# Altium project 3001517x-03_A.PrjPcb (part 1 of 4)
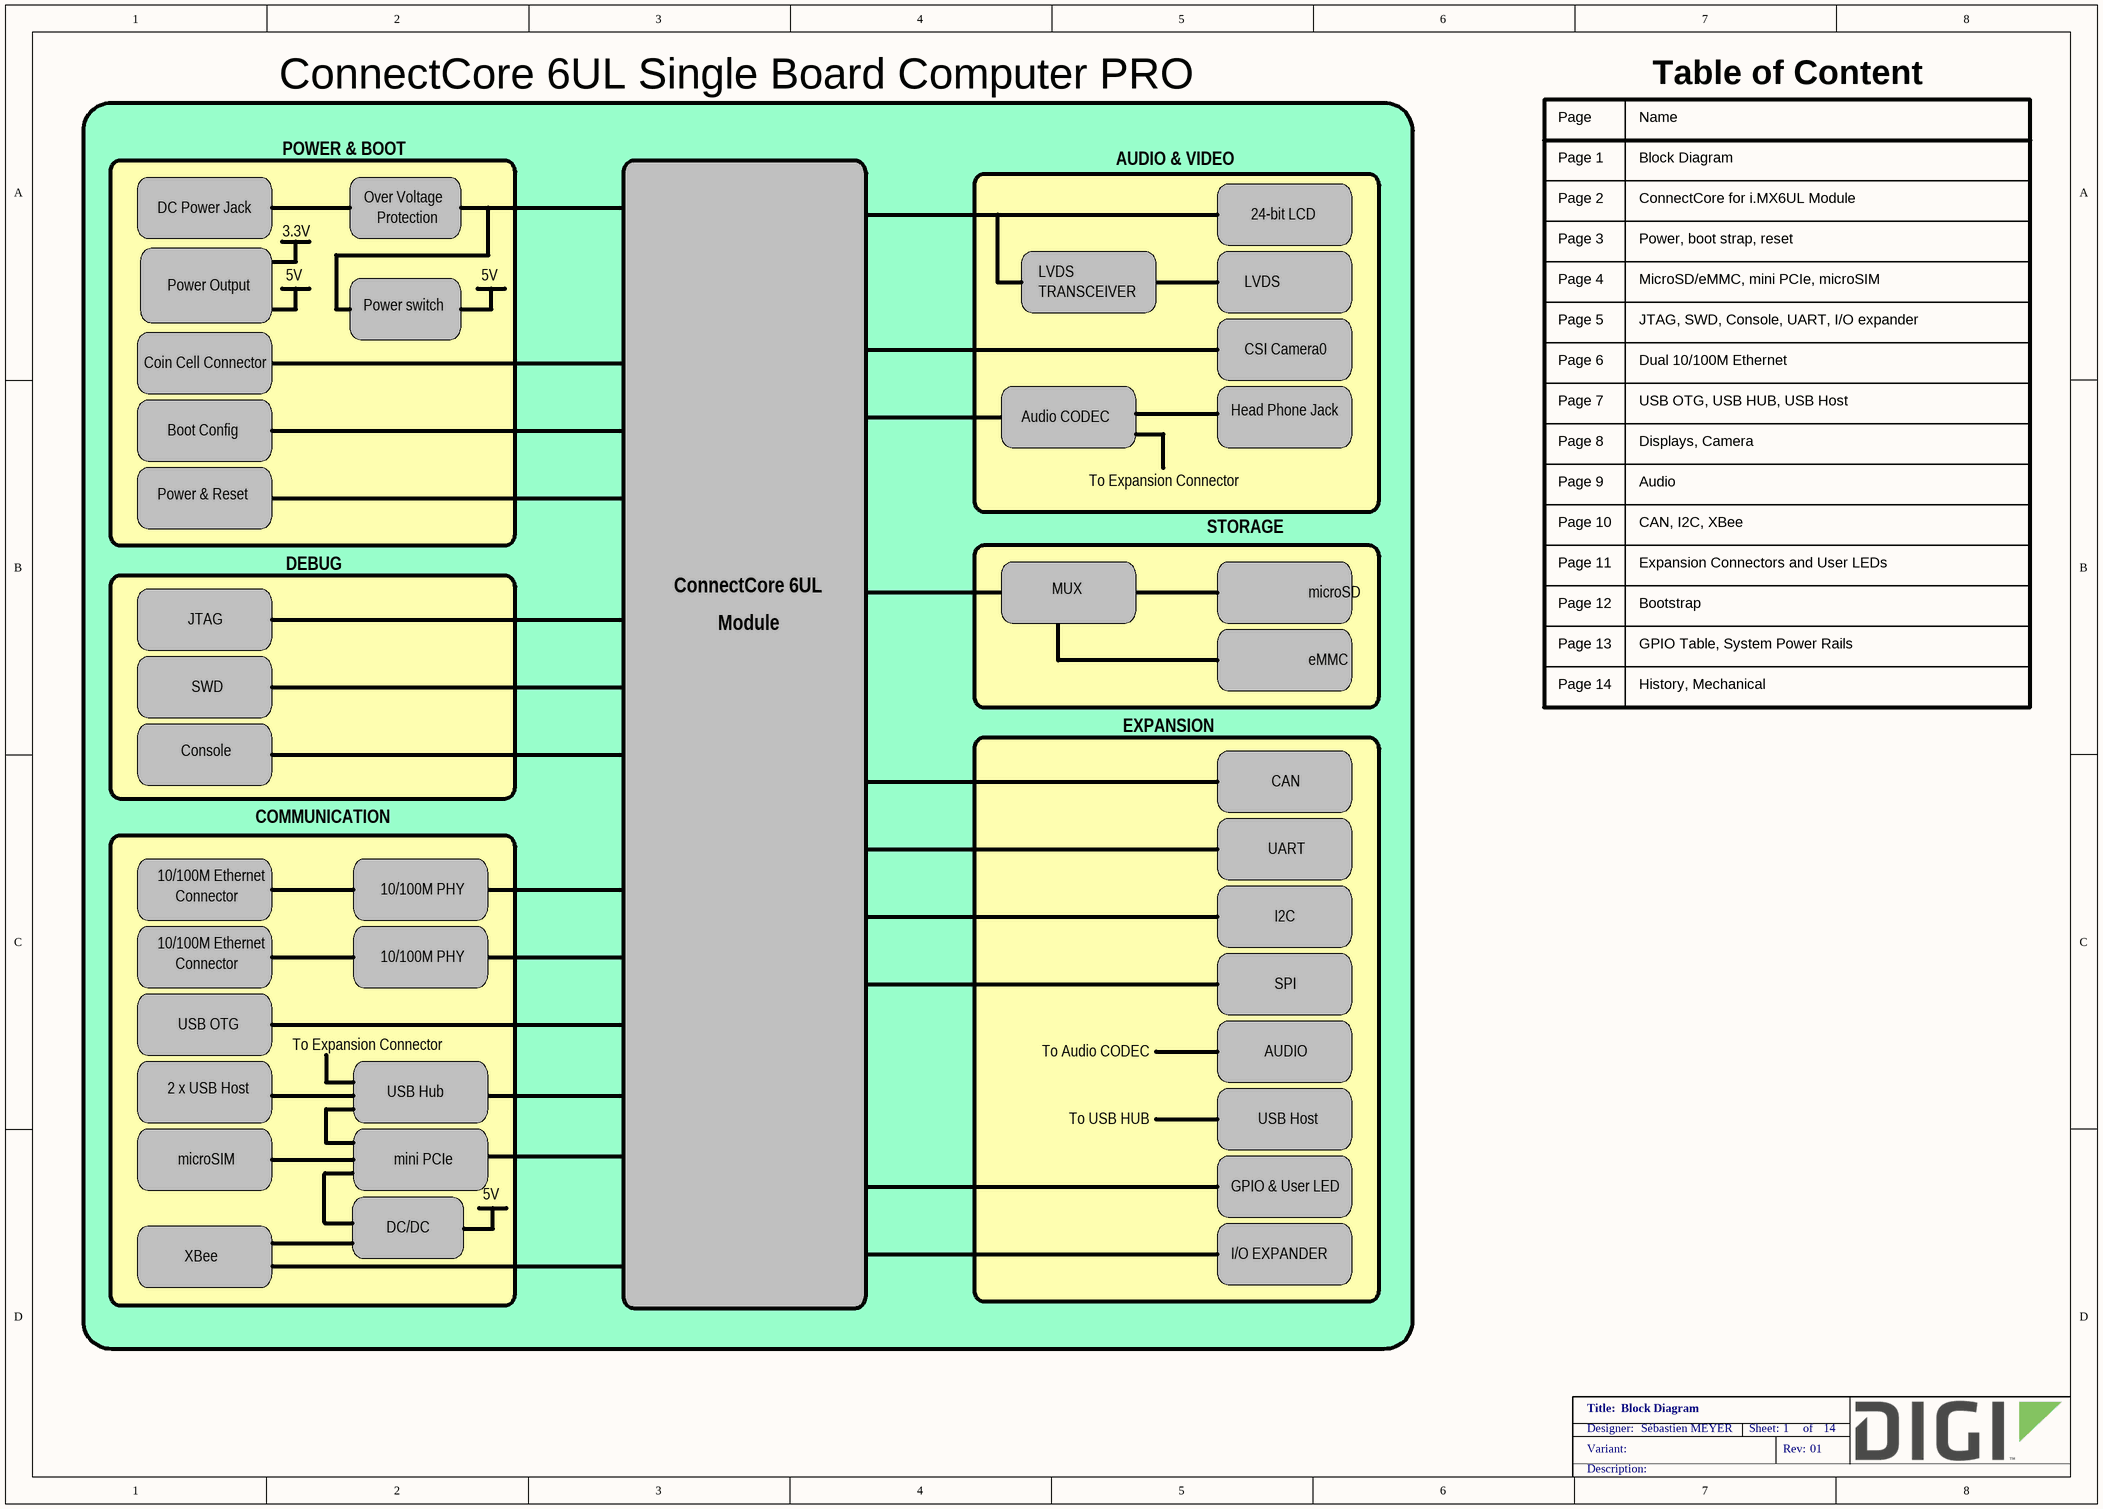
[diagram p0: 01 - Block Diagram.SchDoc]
VariantRevision: 01
14 sheets, 603 parts. Net scope: flat (ports and power ports of the same name join across sheets).
Board file: 3001517x-03_A.PcbDoc
Sheets:
  01 - Block Diagram.SchDoc
  02 - CCIMX6UL Module.SchDoc
  03 - Power, boot strap, reset.SchDoc
  04 - MicroSD, eMMC, Mini PCIe, microSIM.SchDoc
  05 - JTAG, SWD, Console, UART, IO expander.SchDoc
  06 - Ethernet.SchDoc
  07 - USB OTG, USB HUB, USB Host.SchDoc
  08 - Displays and camera.SchDoc
  09 - Audio.SchDoc
  10 - CAN, I2C, XBee.SchDoc
  11 - Expansion Connectors, User LEDs, NTAG.SchDoc
  12 - Bootstrap.SchDoc
  13 - GPIO Table, System Power rails.SchDoc
  14 - History, Mechanicals.SchDoc

## Sheet 01 - Block Diagram.SchDoc: Block Diagram
size A3; PageSetup: Record=PageOptions¦CenterHorizontal=True¦CenterVertical=True¦PrintScale=0.70¦XCorrection=1.00¦YCorrection=1.00¦PrintKind=0¦BorderSize=5000000¦LeftOffset=0¦BottomOffset=0¦Orientation=2¦PaperLength=4200¦PaperWidth=2970¦Scale=100¦PaperSource=7¦PrintQuality=600¦MediaType=1¦DitherType=10¦PaperKind=A4¦PrintScaleMode=1; Author: Sébastien MEYER; SheetNumber: 1; SheetTotal: 14

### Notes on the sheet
- ConnectCore 6UL Single Board Computer PRO
- Table of Content
- POWER & BOOT
- AUDIO & VIDEO
- Page 1
- Page
- Block Diagram
- Name
- DC Power Jack
- 3.3V
- Protection
- Over Voltage
- 24-bit LCD
- Page 2
- Page 3
- ConnectCore for i.MX6UL Module
- Power, boot strap, reset
- Power Output
- 5V
- Power switch
- LVDS
- TRANSCEIVER
- Page 4
- MicroSD/eMMC, mini PCIe, microSIM
- Coin Cell Connector
- CSI Camera0
- Page 5
- Page 6
- Dual 10/100M Ethernet
- JTAG, SWD, Console, UART, I/O expander
- Boot Config
- Audio CODEC
- Head Phone Jack
- Page 7
- Page 8
- Displays, Camera
- USB OTG, USB HUB, USB Host
- Power & Reset
- To Expansion Connector
- Page 9
- Audio
- DEBUG
- STORAGE
- Page 10
- Page 11
- CAN, I2C, XBee
- Expansion Connectors and User LEDs
- JTAG
- ConnectCore 6UL
- Module
- MUX
- microSD
- Page 12
- Page 13
- GPIO Table, System Power Rails
- Bootstrap
- SWD
- eMMC
- Page 14
- History, Mechanical
- Console
- EXPANSION
- CAN
- COMMUNICATION
- UART
- 10/100M Ethernet
- Connector
- 10/100M PHY
- I2C
- SPI
- USB OTG
- To Audio CODEC
- AUDIO
- 2 x USB Host
- USB Hub
- To USB HUB
- USB Host
- microSIM
- mini PCIe
- GPIO & User LED
- XBee
- DC/DC
- I/O EXPANDER

## Sheet 02 - CCIMX6UL Module.SchDoc: ConnectCore for i.MX6UL module
size A2; PageSetup: Record=PageOptions¦CenterHorizontal=True¦CenterVertical=True¦PrintScale=0.71¦XCorrection=1.00¦YCorrection=1.00¦PrintKind=0¦BorderSize=5000000¦LeftOffset=0¦BottomOffset=0¦Orientation=2¦PaperLength=4200¦PaperWidth=2970¦Scale=100¦PaperSource=257¦PrintQuality=600¦MediaType=1¦DitherType=10¦PrintScaleMode=1¦PaperKind=A3¦PaperIndex=8; Author: Sébastien MEYER; SheetNumber: 2; SheetTotal: 14
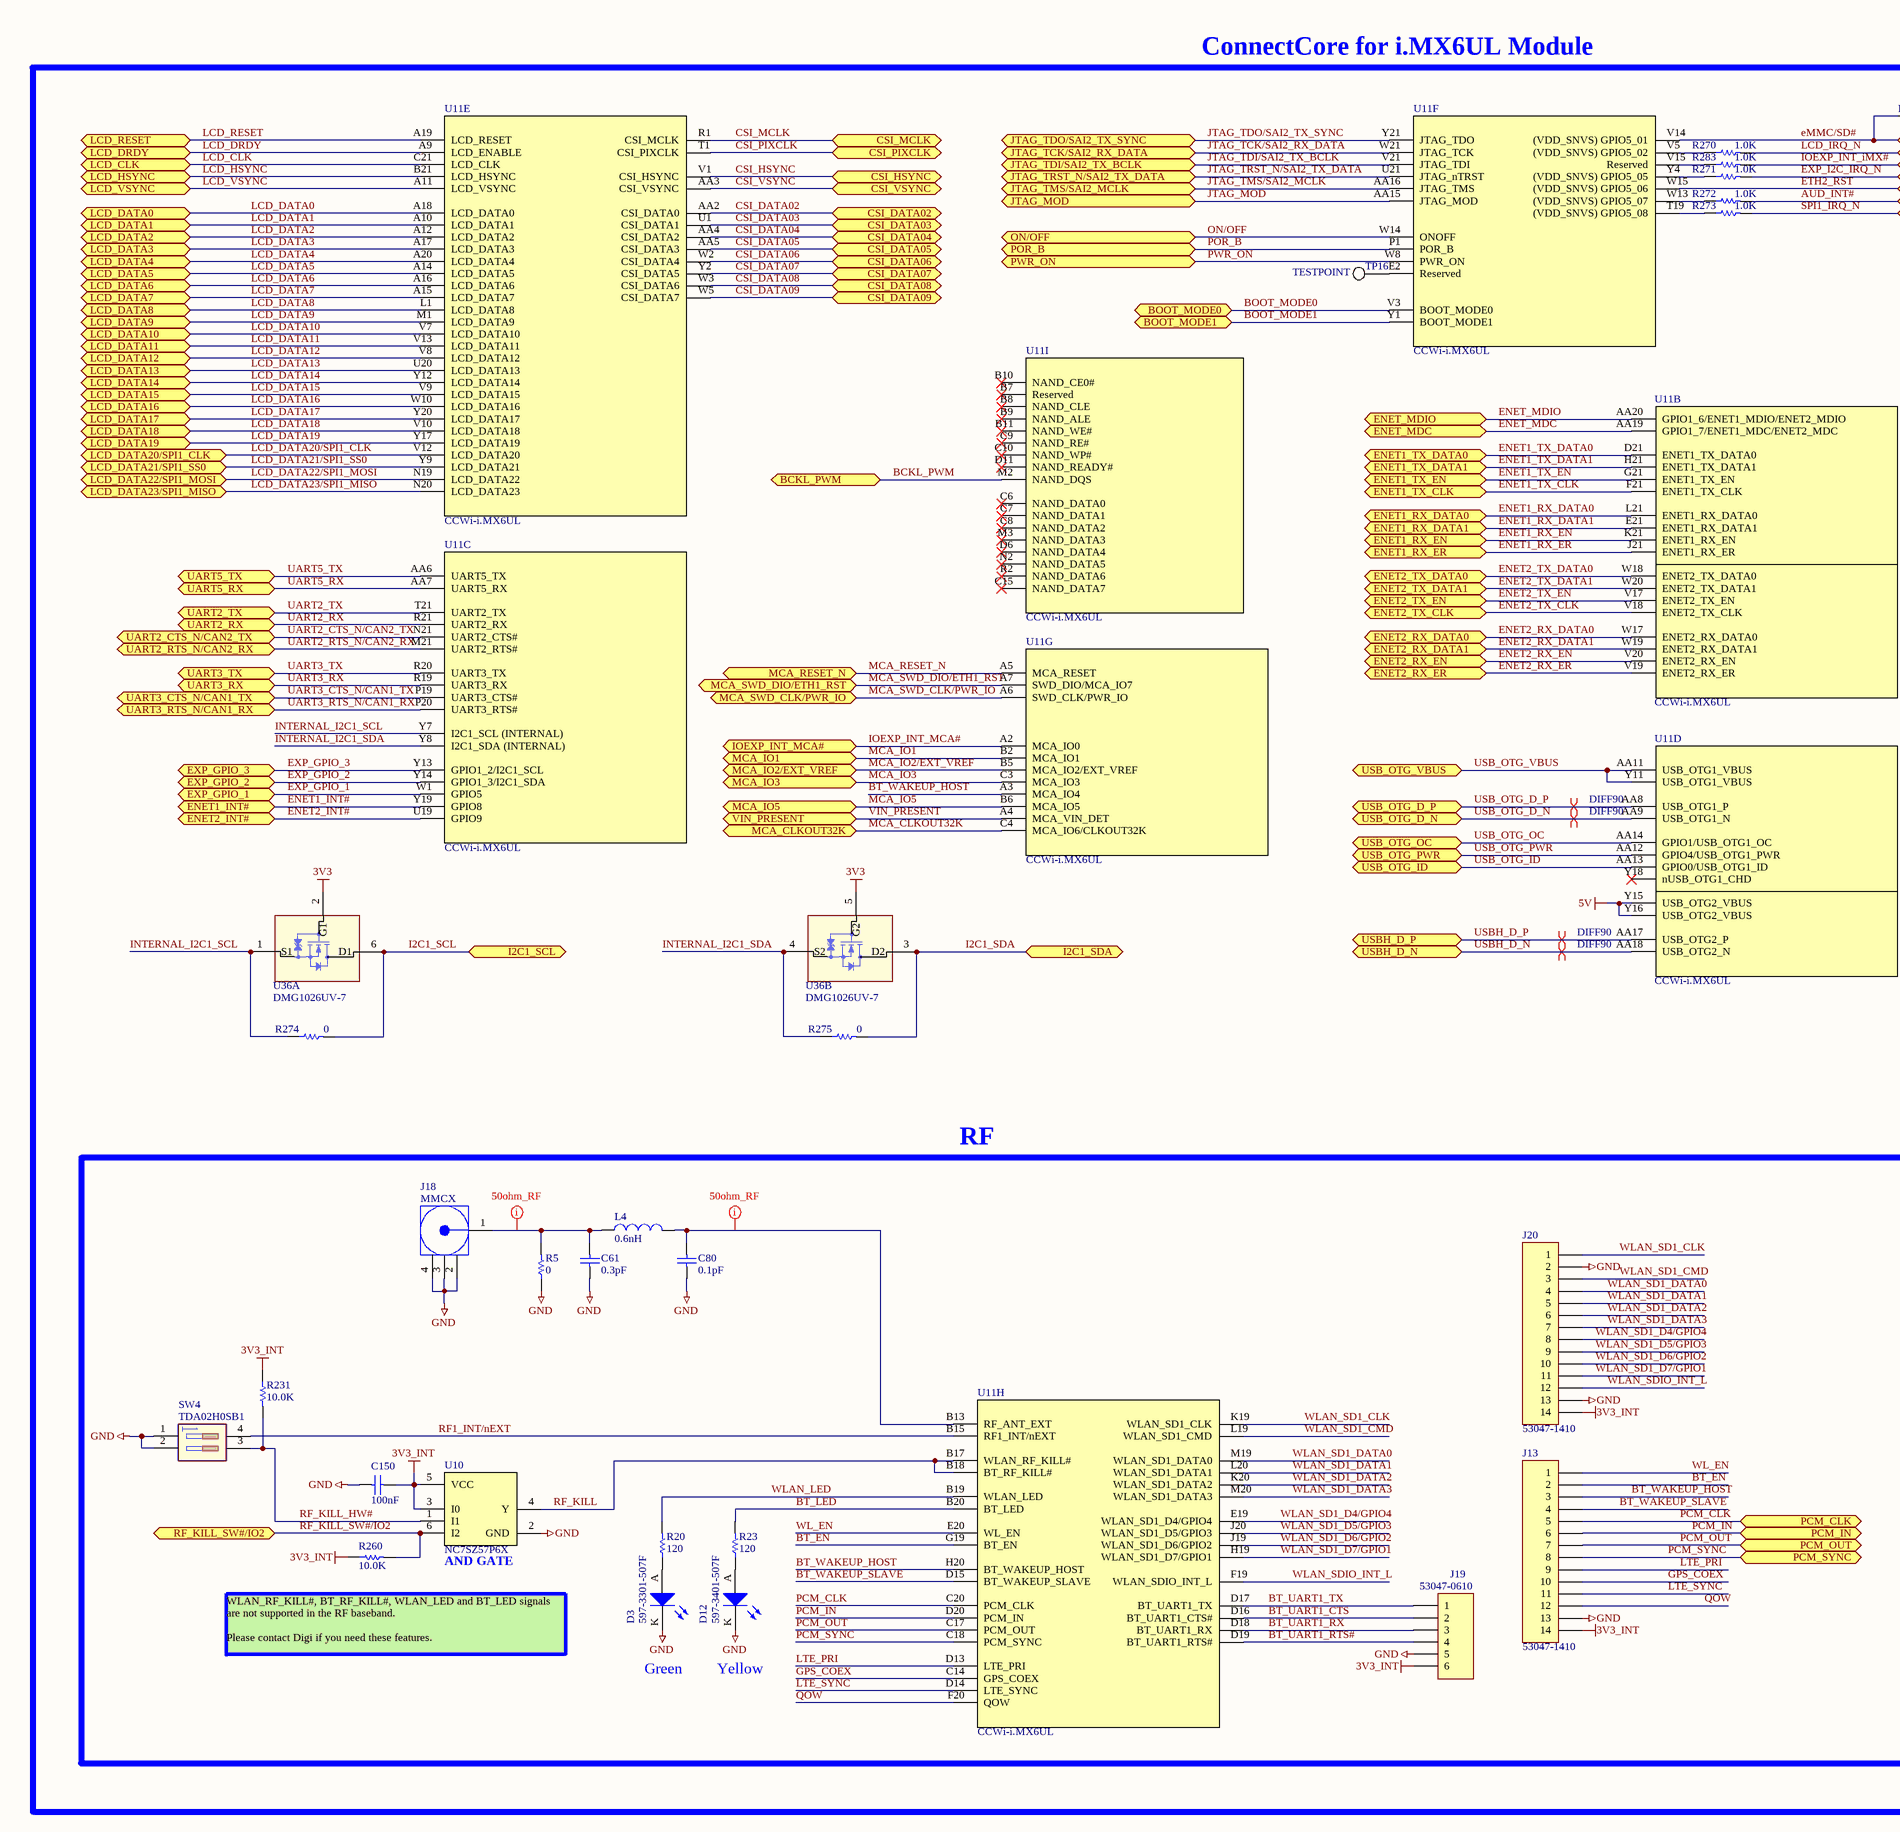
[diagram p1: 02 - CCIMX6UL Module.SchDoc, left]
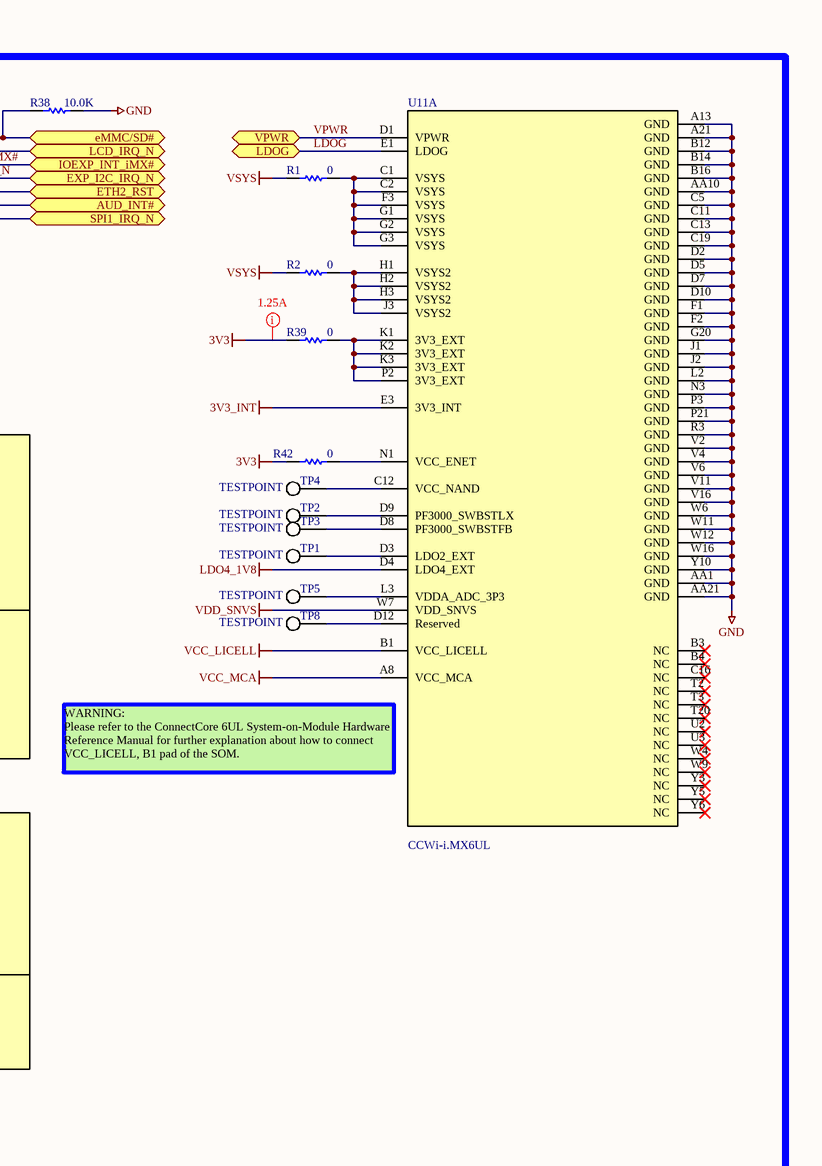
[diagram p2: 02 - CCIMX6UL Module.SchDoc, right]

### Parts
C61  0.3pF  [CAPC0603X33AL]
C80  0.1pF  [CAPC0603X33AL]
C150  100nF  [CAPC1005X55N]
D3  597-3301-507F  [LEDM3020X130N]
D12  597-3401-507F  [LEDM3020X130N]
J13  Manufacturer_Part_Number: 53047-1410  [MOLEX_53047-1410]  (hidden comment: 1x14P)
J18  MMCX  [AMPHENOL_908-22101]
J19  Manufacturer_Part_Number: 53047-0610  [MOLEX_53047-0610]  (hidden comment: 1x6P)
J20  Manufacturer_Part_Number: 53047-1410  [MOLEX_53047-1410]  (hidden comment: 1x14P)
L4  0.6nH  [INDC0603X33N]
R1  0  [RESC1609X55N]
R2  0  [RESC1609X55N]
R5  0  [RESC0603X33AL]
R20  120  [RESC1005X40N]
R23  120  [RESC1005X40N]
R38  10.0K  [RESC1005X40N]
R39  0  [RESC1609X55N]
R42  0  [RESC1005X40N]
R231  10.0K  [RESC1005X40N]
R260  10.0K  [RESC1005X40N]
R270  1.0K  [RESC1005X40N]
R271  1.0K  [RESC1005X40N]
R272  1.0K  [RESC1005X40N]
R273  1.0K  [RESC1005X40N]
R274  0  [RESC1005X40N]
R275  0  [RESC1005X40N]
R283  1.0K  [RESC1005X40N]
SW4  TDA02H0SB1  [SW_TDA02]
TP1  TESTPOINT  [TP0762]  (no BOM)
TP2  TESTPOINT  [TP0762]  (no BOM)
TP3  TESTPOINT  [TP0762]  (no BOM)
TP4  TESTPOINT  [TP0762]  (no BOM)
TP5  TESTPOINT  [TP0762]  (no BOM)
TP8  TESTPOINT  [TP0762]  (no BOM)
TP16  TESTPOINT  [TP0762]  (no BOM)
U10  NC7SZ57P6X  [SOT65P210X110-6N]
U11  CCWi-i.MX6UL  [CC6UL_LGA]  (parts A,B,C,D,E,F,G,H,I of 9)
U36  DMG1026UV-7  [SOTFL50P160X60-6N]  (parts A,B of 2)

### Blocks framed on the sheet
RF: C61 C80 C150 D3 D12 J13 J18-J20 L4 R5 R20 R23 R231 R260 SW4 U10 U11

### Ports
AUD_INT# (bidir), BCKL_PWM (bidir), BOOT_MODE0 (bidir), BOOT_MODE1 (bidir), CSI_DATA02 (bidir), CSI_DATA03 (bidir), CSI_DATA04 (bidir), CSI_DATA05 (bidir), CSI_DATA06 (bidir), CSI_DATA07 (bidir), CSI_DATA08 (bidir), CSI_DATA09 (bidir), CSI_HSYNC (bidir), CSI_MCLK (bidir), CSI_PIXCLK (bidir), CSI_VSYNC (bidir), eMMC/SD# (bidir), ENET1_INT# (bidir), ENET1_RX_DATA0 (bidir), ENET1_RX_DATA1 (bidir), ENET1_RX_EN (bidir), ENET1_RX_ER (bidir), ENET1_TX_CLK (bidir), ENET1_TX_DATA0 (bidir), ENET1_TX_DATA1 (bidir), ENET1_TX_EN (bidir), ENET2_INT# (bidir), ENET2_RX_DATA0 (bidir), ENET2_RX_DATA1 (bidir), ENET2_RX_EN (bidir), ENET2_RX_ER (bidir), ENET2_TX_CLK (bidir), ENET2_TX_DATA0 (bidir), ENET2_TX_DATA1 (bidir), ENET2_TX_EN (bidir), ENET_MDC (bidir), ENET_MDIO (bidir), ETH2_RST (bidir), EXP_GPIO_1 (bidir), EXP_GPIO_2 (bidir), EXP_GPIO_3 (bidir), EXP_I2C_IRQ_N (bidir), I2C1_SCL (bidir), I2C1_SDA (bidir), IOEXP_INT_iMX# (bidir), IOEXP_INT_MCA# (bidir), JTAG_MOD (bidir), JTAG_TCK/SAI2_RX_DATA (bidir), JTAG_TDI/SAI2_TX_BCLK (bidir), JTAG_TDO/SAI2_TX_SYNC (bidir), JTAG_TMS/SAI2_MCLK (bidir), JTAG_TRST_N/SAI2_TX_DATA (bidir), LCD_CLK (bidir), LCD_DATA0 (bidir), LCD_DATA1 (bidir), LCD_DATA2 (bidir), LCD_DATA3 (bidir), LCD_DATA4 (bidir), LCD_DATA5 (bidir), LCD_DATA6 (bidir), LCD_DATA7 (bidir), LCD_DATA8 (bidir), LCD_DATA9 (bidir), LCD_DATA10 (bidir), LCD_DATA11 (bidir), LCD_DATA12 (bidir), LCD_DATA13 (bidir), LCD_DATA14 (bidir), LCD_DATA15 (bidir), LCD_DATA16 (bidir), LCD_DATA17 (bidir), LCD_DATA18 (bidir), LCD_DATA19 (bidir), LCD_DATA20/SPI1_CLK (bidir), LCD_DATA21/SPI1_SS0 (bidir), LCD_DATA22/SPI1_MOSI (bidir), LCD_DATA23/SPI1_MISO (bidir), LCD_DRDY (bidir), LCD_HSYNC (bidir), LCD_IRQ_N (bidir), LCD_RESET (bidir), LCD_VSYNC (bidir), LDOG (bidir), MCA_CLKOUT32K (bidir), MCA_IO1 (bidir), MCA_IO2/EXT_VREF (bidir), MCA_IO3 (bidir), MCA_IO5 (bidir), MCA_RESET_N (bidir), MCA_SWD_CLK/PWR_IO (bidir), MCA_SWD_DIO/ETH1_RST (bidir), ON/OFF (bidir), PCM_CLK (bidir), PCM_IN (bidir), PCM_OUT (bidir), PCM_SYNC (bidir), POR_B (bidir), PWR_ON (bidir), RF_KILL_SW#/IO2 (bidir), SPI1_IRQ_N (bidir), UART2_CTS_N/CAN2_TX (bidir), UART2_RTS_N/CAN2_RX (bidir), UART2_RX (bidir), UART2_TX (bidir), UART3_CTS_N/CAN1_TX (bidir), UART3_RTS_N/CAN1_RX (bidir), UART3_RX (bidir), UART3_TX (bidir), UART5_RX (bidir), UART5_TX (bidir), USB_OTG_D_N (bidir), USB_OTG_D_P (bidir), USB_OTG_ID (bidir), USB_OTG_OC (bidir), USB_OTG_PWR (bidir), USB_OTG_VBUS (bidir), USBH_D_N (bidir), USBH_D_P (bidir), VIN_PRESENT (bidir), VPWR (bidir)

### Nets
3V3: R39.1 R42.1 U36.2(G1) U36.5(G2)
3V3_INT: C150.2 J13.14 J19.6 J20.14 R231.1 R260.1 U10.3(I0) U10.5(VCC) U11.E3(3V3_INT)
5V: U11.Y15(USB_OTG2_VBUS) U11.Y16(USB_OTG2_VBUS)
GND: C61.1 C80.1 C150.1 D3.K D12.K J13.13 J18.2(GND) J18.3(GND) J18.4 J19.5 J20.2 J20.13 R5.1 R38.2 SW4.1(A1) SW4.2(A2) U10.2(GND) U11.A13(GND) U11.A21(GND) U11.AA1(GND) U11.AA10(GND) U11.AA21(GND) U11.B12(GND) U11.B14(GND) U11.B16(GND) U11.C5(GND) U11.C11(GND) U11.C13(GND) U11.C19(GND) U11.D2(GND) U11.D5(GND) U11.D7(GND) U11.D10(GND) U11.F1(GND) U11.F2(GND) U11.G20(GND) U11.J1(GND) U11.J2(GND) U11.L2(GND) U11.N3(GND) U11.P3(GND) U11.P21(GND) U11.R3(GND) U11.V2(GND) U11.V4(GND) U11.V6(GND) U11.V11(GND) U11.V16(GND) U11.W6(GND) U11.W11(GND) U11.W12(GND) U11.W16(GND) U11.Y10(GND)
LDO4_1V8: U11.D4(LDO4_EXT)
VCC_LICELL: U11.B1(VCC_LICELL)
VCC_MCA: U11.A8(VCC_MCA)
VDD_SNVS: U11.W7(VDD_SNVS)
VSYS: R1.1 R2.1
AUD_INT#: R272.2 ; port AUD_INT#
BCKL_PWM: U11.M2(NAND_DQS) ; port BCKL_PWM
BOOT_MODE0: U11.V3(BOOT_MODE0) ; port BOOT_MODE0
BOOT_MODE1: U11.Y1(BOOT_MODE1) ; port BOOT_MODE1
BT_EN: J13.2 U11.G19(BT_EN)
BT_LED: R23.2 U11.B20(BT_LED)
BT_UART1_CTS: J19.2 U11.D16(BT_UART1_CTS#)
BT_UART1_RTS#: J19.4 U11.D19(BT_UART1_RTS#)
BT_UART1_RX: J19.3 U11.D18(BT_UART1_RX)
BT_UART1_TX: J19.1 U11.D17(BT_UART1_TX)
BT_WAKEUP_HOST: J13.3 U11.A3(MCA_IO4) U11.H20(BT_WAKEUP_HOST)
BT_WAKEUP_SLAVE: J13.4 U11.D15(BT_WAKEUP_SLAVE)
CSI_DATA02: U11.AA2(CSI_DATA0) ; port CSI_DATA02
CSI_DATA03: U11.U1(CSI_DATA1) ; port CSI_DATA03
CSI_DATA04: U11.AA4(CSI_DATA2) ; port CSI_DATA04
CSI_DATA05: U11.AA5(CSI_DATA3) ; port CSI_DATA05
CSI_DATA06: U11.W2(CSI_DATA4) ; port CSI_DATA06
CSI_DATA07: U11.Y2(CSI_DATA5) ; port CSI_DATA07
CSI_DATA08: U11.W3(CSI_DATA6) ; port CSI_DATA08
CSI_DATA09: U11.W5(CSI_DATA7) ; port CSI_DATA09
CSI_HSYNC: U11.V1(CSI_HSYNC) ; port CSI_HSYNC
CSI_MCLK: U11.R1(CSI_MCLK) ; port CSI_MCLK
CSI_PIXCLK: U11.T1(CSI_PIXCLK) ; port CSI_PIXCLK
CSI_VSYNC: U11.AA3(CSI_VSYNC) ; port CSI_VSYNC
eMMC/SD#: R38.1 U11.V14((VDD_SNVS)_GPIO5_01) ; port eMMC/SD#
ENET1_INT#: U11.Y19(GPIO8) ; port ENET1_INT#
ENET1_RX_DATA0: U11.L21(ENET1_RX_DATA0) ; port ENET1_RX_DATA0
ENET1_RX_DATA1: U11.E21(ENET1_RX_DATA1) ; port ENET1_RX_DATA1
ENET1_RX_EN: U11.K21(ENET1_RX_EN) ; port ENET1_RX_EN
ENET1_RX_ER: U11.J21(ENET1_RX_ER) ; port ENET1_RX_ER
ENET1_TX_CLK: U11.F21(ENET1_TX_CLK) ; port ENET1_TX_CLK
ENET1_TX_DATA0: U11.D21(ENET1_TX_DATA0) ; port ENET1_TX_DATA0
ENET1_TX_DATA1: U11.H21(ENET1_TX_DATA1) ; port ENET1_TX_DATA1
ENET1_TX_EN: U11.G21(ENET1_TX_EN) ; port ENET1_TX_EN
ENET2_INT#: U11.U19(GPIO9) ; port ENET2_INT#
ENET2_RX_DATA0: U11.W17(ENET2_RX_DATA0) ; port ENET2_RX_DATA0
ENET2_RX_DATA1: U11.W19(ENET2_RX_DATA1) ; port ENET2_RX_DATA1
ENET2_RX_EN: U11.V20(ENET2_RX_EN) ; port ENET2_RX_EN
ENET2_RX_ER: U11.V19(ENET2_RX_ER) ; port ENET2_RX_ER
ENET2_TX_CLK: U11.V18(ENET2_TX_CLK) ; port ENET2_TX_CLK
ENET2_TX_DATA0: U11.W18(ENET2_TX_DATA0) ; port ENET2_TX_DATA0
ENET2_TX_DATA1: U11.W20(ENET2_TX_DATA1) ; port ENET2_TX_DATA1
ENET2_TX_EN: U11.V17(ENET2_TX_EN) ; port ENET2_TX_EN
ENET_MDC: U11.AA19(GPIO1_7/ENET1_MDC/ENET2_MDC) ; port ENET_MDC
ENET_MDIO: U11.AA20(GPIO1_6/ENET1_MDIO/ENET2_MDIO) ; port ENET_MDIO
ETH2_RST: U11.W15((VDD_SNVS)_GPIO5_06) ; port ETH2_RST
EXP_GPIO_1: U11.W1(GPIO5) ; port EXP_GPIO_1
EXP_GPIO_2: U11.Y14(GPIO1_3/I2C1_SDA) ; port EXP_GPIO_2
EXP_GPIO_3: U11.Y13(GPIO1_2/I2C1_SCL) ; port EXP_GPIO_3
EXP_I2C_IRQ_N: R271.2 ; port EXP_I2C_IRQ_N
GPS_COEX: J13.10 U11.C14(GPS_COEX)
I2C1_SCL: R274.2 U36.6(D1) ; port I2C1_SCL
I2C1_SDA: R275.2 U36.3(D2) ; port I2C1_SDA
INTERNAL_I2C1_SCL: R274.1 U11.Y7(I2C1_SCL_(INTERNAL)) U36.1(S1)
INTERNAL_I2C1_SDA: R275.1 U11.Y8(I2C1_SDA_(INTERNAL)) U36.4(S2)
IOEXP_INT_iMX#: R283.2 ; port IOEXP_INT_iMX#
IOEXP_INT_MCA#: U11.A2(MCA_IO0) ; port IOEXP_INT_MCA#
JTAG_MOD: U11.AA15(JTAG_MOD) ; port JTAG_MOD
JTAG_TCK/SAI2_RX_DATA: U11.W21(JTAG_TCK) ; port JTAG_TCK/SAI2_RX_DATA
JTAG_TDI/SAI2_TX_BCLK: U11.V21(JTAG_TDI) ; port JTAG_TDI/SAI2_TX_BCLK
JTAG_TDO/SAI2_TX_SYNC: U11.Y21(JTAG_TDO) ; port JTAG_TDO/SAI2_TX_SYNC
JTAG_TMS/SAI2_MCLK: U11.AA16(JTAG_TMS) ; port JTAG_TMS/SAI2_MCLK
JTAG_TRST_N/SAI2_TX_DATA: U11.U21(JTAG_nTRST) ; port JTAG_TRST_N/SAI2_TX_DATA
LCD_CLK: U11.C21(LCD_CLK) ; port LCD_CLK
LCD_DATA0: U11.A18(LCD_DATA0) ; port LCD_DATA0
LCD_DATA1: U11.A10(LCD_DATA1) ; port LCD_DATA1
LCD_DATA2: U11.A12(LCD_DATA2) ; port LCD_DATA2
LCD_DATA3: U11.A17(LCD_DATA3) ; port LCD_DATA3
LCD_DATA4: U11.A20(LCD_DATA4) ; port LCD_DATA4
LCD_DATA5: U11.A14(LCD_DATA5) ; port LCD_DATA5
LCD_DATA6: U11.A16(LCD_DATA6) ; port LCD_DATA6
LCD_DATA7: U11.A15(LCD_DATA7) ; port LCD_DATA7
LCD_DATA8: U11.L1(LCD_DATA8) ; port LCD_DATA8
LCD_DATA9: U11.M1(LCD_DATA9) ; port LCD_DATA9
LCD_DATA10: U11.V7(LCD_DATA10) ; port LCD_DATA10
LCD_DATA11: U11.V13(LCD_DATA11) ; port LCD_DATA11
LCD_DATA12: U11.V8(LCD_DATA12) ; port LCD_DATA12
LCD_DATA13: U11.U20(LCD_DATA13) ; port LCD_DATA13
LCD_DATA14: U11.Y12(LCD_DATA14) ; port LCD_DATA14
LCD_DATA15: U11.V9(LCD_DATA15) ; port LCD_DATA15
LCD_DATA16: U11.W10(LCD_DATA16) ; port LCD_DATA16
LCD_DATA17: U11.Y20(LCD_DATA17) ; port LCD_DATA17
LCD_DATA18: U11.V10(LCD_DATA18) ; port LCD_DATA18
LCD_DATA19: U11.Y17(LCD_DATA19) ; port LCD_DATA19
LCD_DATA20/SPI1_CLK: U11.V12(LCD_DATA20) ; port LCD_DATA20/SPI1_CLK
LCD_DATA21/SPI1_SS0: U11.Y9(LCD_DATA21) ; port LCD_DATA21/SPI1_SS0
LCD_DATA22/SPI1_MOSI: U11.N19(LCD_DATA22) ; port LCD_DATA22/SPI1_MOSI
LCD_DATA23/SPI1_MISO: U11.N20(LCD_DATA23) ; port LCD_DATA23/SPI1_MISO
LCD_DRDY: U11.A9(LCD_ENABLE) ; port LCD_DRDY
LCD_HSYNC: U11.B21(LCD_HSYNC) ; port LCD_HSYNC
LCD_IRQ_N: R270.2 ; port LCD_IRQ_N
LCD_RESET: U11.A19(LCD_RESET) ; port LCD_RESET
LCD_VSYNC: U11.A11(LCD_VSYNC) ; port LCD_VSYNC
LDOG: U11.E1(LDOG) ; port LDOG
LTE_PRI: J13.9 U11.D13(LTE_PRI)
LTE_SYNC: J13.11 U11.D14(LTE_SYNC)
MCA_CLKOUT32K: U11.C4(MCA_IO6/CLKOUT32K) ; port MCA_CLKOUT32K
MCA_IO1: U11.B2(MCA_IO1) ; port MCA_IO1
MCA_IO2/EXT_VREF: U11.B5(MCA_IO2/EXT_VREF) ; port MCA_IO2/EXT_VREF
MCA_IO3: U11.C3(MCA_IO3) ; port MCA_IO3
MCA_IO5: U11.B6(MCA_IO5) ; port MCA_IO5
MCA_RESET_N: U11.A5(MCA_RESET) ; port MCA_RESET_N
MCA_SWD_CLK/PWR_IO: U11.A6(SWD_CLK/PWR_IO) ; port MCA_SWD_CLK/PWR_IO
MCA_SWD_DIO/ETH1_RST: U11.A7(SWD_DIO/MCA_IO7) ; port MCA_SWD_DIO/ETH1_RST
ON/OFF: U11.W14(ONOFF) ; port ON/OFF
PCM_CLK: J13.5 U11.C20(PCM_CLK) ; port PCM_CLK
PCM_IN: J13.6 U11.D20(PCM_IN) ; port PCM_IN
PCM_OUT: J13.7 U11.C17(PCM_OUT) ; port PCM_OUT
PCM_SYNC: J13.8 U11.C18(PCM_SYNC) ; port PCM_SYNC
POR_B: U11.P1(POR_B) ; port POR_B
PWR_ON: U11.W8(PWR_ON) ; port PWR_ON
QOW: J13.12 U11.F20(QOW)
RF1_INT/nEXT: SW4.4(B1) U11.B15(RF1_INT/nEXT)
RF_KILL: U10.4(Y) U11.B17(WLAN_RF_KILL#) U11.B18(BT_RF_KILL#)
RF_KILL_HW#: R231.2 SW4.3(B2) U10.1(I1)
RF_KILL_SW#/IO2: R260.2 U10.6(I2) ; port RF_KILL_SW#/IO2
SPI1_IRQ_N: R273.2 ; port SPI1_IRQ_N
UART2_CTS_N/CAN2_TX: U11.N21(UART2_CTS#) ; port UART2_CTS_N/CAN2_TX
UART2_RTS_N/CAN2_RX: U11.M21(UART2_RTS#) ; port UART2_RTS_N/CAN2_RX
UART2_RX: U11.R21(UART2_RX) ; port UART2_RX
UART2_TX: U11.T21(UART2_TX) ; port UART2_TX
UART3_CTS_N/CAN1_TX: U11.P19(UART3_CTS#) ; port UART3_CTS_N/CAN1_TX
UART3_RTS_N/CAN1_RX: U11.P20(UART3_RTS#) ; port UART3_RTS_N/CAN1_RX
UART3_RX: U11.R19(UART3_RX) ; port UART3_RX
UART3_TX: U11.R20(UART3_TX) ; port UART3_TX
UART5_RX: U11.AA7(UART5_RX) ; port UART5_RX
UART5_TX: U11.AA6(UART5_TX) ; port UART5_TX
USB_OTG_D_N: U11.AA9(USB_OTG1_N) ; port USB_OTG_D_N
USB_OTG_D_P: U11.AA8(USB_OTG1_P) ; port USB_OTG_D_P
USB_OTG_ID: U11.AA13(GPIO0/USB_OTG1_ID) ; port USB_OTG_ID
USB_OTG_OC: U11.AA14(GPIO1/USB_OTG1_OC) ; port USB_OTG_OC
USB_OTG_PWR: U11.AA12(GPIO4/USB_OTG1_PWR) ; port USB_OTG_PWR
USB_OTG_VBUS: U11.AA11(USB_OTG1_VBUS) U11.Y11(USB_OTG1_VBUS) ; port USB_OTG_VBUS
USBH_D_N: U11.AA18(USB_OTG2_N) ; port USBH_D_N
USBH_D_P: U11.AA17(USB_OTG2_P) ; port USBH_D_P
VIN_PRESENT: U11.A4(MCA_VIN_DET) ; port VIN_PRESENT
VPWR: U11.D1(VPWR) ; port VPWR
WL_EN: J13.1 U11.E20(WL_EN)
WLAN_LED: R20.2 U11.B19(WLAN_LED)
WLAN_SD1_CLK: J20.1 U11.K19(WLAN_SD1_CLK)
WLAN_SD1_CMD: J20.3 U11.L19(WLAN_SD1_CMD)
WLAN_SD1_D4/GPIO4: J20.8 U11.E19(WLAN_SD1_D4/GPIO4)
WLAN_SD1_D5/GPIO3: J20.9 U11.J20(WLAN_SD1_D5/GPIO3)
WLAN_SD1_D6/GPIO2: J20.10 U11.J19(WLAN_SD1_D6/GPIO2)
WLAN_SD1_D7/GPIO1: J20.11 U11.H19(WLAN_SD1_D7/GPIO1)
WLAN_SD1_DATA0: J20.4 U11.M19(WLAN_SD1_DATA0)
WLAN_SD1_DATA1: J20.5 U11.L20(WLAN_SD1_DATA1)
WLAN_SD1_DATA2: J20.6 U11.K20(WLAN_SD1_DATA2)
WLAN_SD1_DATA3: J20.7 U11.M20(WLAN_SD1_DATA3)
WLAN_SDIO_INT_L: J20.12 U11.F19(WLAN_SDIO_INT_L)
NetC61_2: C61.2 J18.1(Signal) L4.1 R5.2
NetC80_2: C80.2 L4.2 U11.B13(RF_ANT_EXT)
NetD3_A: D3.A R20.1
NetD12_A: D12.A R23.1
NetR1_2: R1.2 U11.C1(VSYS) U11.C2(VSYS) U11.F3(VSYS) U11.G1(VSYS) U11.G2(VSYS) U11.G3(VSYS)
NetR2_2: R2.2 U11.H1(VSYS2) U11.H2(VSYS2) U11.H3(VSYS2) U11.J3(VSYS2)
NetR39_2: R39.2 U11.K1(3V3_EXT) U11.K2(3V3_EXT) U11.K3(3V3_EXT) U11.P2(3V3_EXT)
NetR42_2: R42.2 U11.N1(VCC_ENET)
NetR270_1: R270.1 U11.V5((VDD_SNVS)_GPIO5_02)
NetR271_1: R271.1 U11.Y4((VDD_SNVS)_GPIO5_05)
NetR272_1: R272.1 U11.W13((VDD_SNVS)_GPIO5_07)
NetR273_1: R273.1 U11.T19((VDD_SNVS)_GPIO5_08)
NetR283_1: R283.1 U11.V15(Reserved)
NetTP1_1: TP1.1 U11.D3(LDO2_EXT)
NetTP2_1: TP2.1 U11.D9(PF3000_SWBSTLX)
NetTP3_1: TP3.1 U11.D8(PF3000_SWBSTFB)
NetTP4_1: TP4.1 U11.C12(VCC_NAND)
NetTP5_1: TP5.1 U11.L3(VDDA_ADC_3P3)
NetTP8_1: TP8.1 U11.D12(Reserved)
NetTP16_1: TP16.1 U11.E2(Reserved)

Not connected (* = marked no-connect by the designer): U11 B3(NC)* B4(NC)* B7(Reserved)* B8(NAND_CLE)* B9(NAND_ALE)* B10(NAND_CE0#)* B11(NAND_WE#)* C6(NAND_DATA0)* C7(NAND_DATA1)* C8(NAND_DATA2)* C9(NAND_RE#)* C10(NAND_WP#)* C15(NAND_DATA7)* C16(NC)* D6(NAND_DATA4)* D11(NAND_READY#)* M3(NAND_DATA3)* N2(NAND_DATA5)* R2(NAND_DATA6)* T2(NC)* T3(NC)* T20(NC)* U2(NC)* U3(NC)* W4(NC)* W9(NC)* Y3(NC)* Y5(NC)* Y6(NC)* Y18(nUSB_OTG1_CHD)*

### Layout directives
differential pair; net class DIFF90: USB_OTG_D_N, USB_OTG_D_P, USBH_D_N, USBH_D_P
net class 50ohm_RF: NetC61_2, NetC80_2
net class 1.25A: 3V3

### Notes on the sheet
- ConnectCore for i.MX6UL Module
- (near U11) WARNING:
  Please refer to the ConnectCore 6UL System-on-Module Hardware Reference Manual for further explanation about how to connect VCC_LICELL, B1 pad of the SOM.
- (near U10) AND GATE
- (near R260) WLAN_RF_KILL#, BT_RF_KILL#, WLAN_LED and BT_LED signals are not supported in the RF baseband.
  Please contact Digi if you need these features.
- Green
- Yellow

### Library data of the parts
C61 = 1001848: CAP CER 0.3PF 25V NP0 0201 +/-0.1pF; Part_Type: Capacitor; Manufacturer: Murata; Manufacturer_Part_Number: GRM0335C1ER30BZ01D; Digi_PN: 14050576; Component_Life_Cycle_State: Reviewed; Area: 1.4; Project: iMX6UL+PMIC; Tolerance: 0.1; Temp_Coef: C0G, NP0
C80 = 1001847: CAP CER 0.1PF 25V NP0 0201 +/-0.05pF; Part_Type: Capacitor; Manufacturer: Murata; Manufacturer_Part_Number: GRM0335C1ER10WA01D; Component_Life_Cycle_State: Reviewed; Area: 1,4; Project: iMX6UL+PMIC; Tolerance: 0.05; Temp_Coef: C0G, NP0; Digi_PN: 14050774
C150 = 1000006: CAP 100nF 16V 10% X7R 0402; Part_Type: Capacitor; Manufacturer: Murata; Manufacturer_Part_Number: GRM155R71C104KA88D; Component_Life_Cycle_State: CAD Reviewed; Area: 0.95; Project: KITT; Tolerance: 10; Digi_PN: 14050552
D3 = 1001189: LED GREEN 573NM 1208 SMD; Manufacturer: Dialight; Digi_PN: 17050183; Component_Life_Cycle_State: Reviewed; Area: 6; Project: CCWMX6_SBC board; Note: 17050846 = Digi PN for GE WDNU II
D12 = 1001188: LED YELLOW 588NM 1208 SMD; Manufacturer: Dialight; Digi_PN: 17050387; Component_Life_Cycle_State: Reviewed; Area: 6; Project: CCWMX6_SBC board; Note: 17050842 = Digi No. for GE WDNU
J13 J20 = 1001140: CONN HEADER 14POS 1.25MM STR TIN; Part_Type: Connector; Manufacturer: Molex; Digi_PN: 18050347; Component_Life_Cycle_State: Reviewed; Area: 61.6; Project: CCWMX6_SBC board
J18 = 1002018: CONN MMCX JACK STR 50 OHM SMD; Part_Type: Connector; Manufacturer: Amphenol; Manufacturer_Part_Number: 908-22101; Digi_PN: 18000617; Component_Life_Cycle_State: Created; Area: 32.09; Project: iMX6UL+PMIC
J19 = 1001138: CONN HEADER 6POS 1.25MM VERT TIN; Part_Type: Connector; Manufacturer: Molex; Digi_PN: 18050345; Component_Life_Cycle_State: Reviewed; Area: 29.6; Project: CCWMX6_SBC board
L4 = 1001850: FIXED IND 0.6NH 850MA 70 MOHM +/-0.1nH; Manufacturer: Murata; Manufacturer_Part_Number: LQP03TN0N6B02D; Component_Life_Cycle_State: Reviewed; Area: 1,09; Project: iMX6UL+PMIC; Tolerance: ±0.1uH; Digi_PN: 21000536
R1 R2 R39 = 1000208: RES 0.0 OHM 1/10W 0603; Part_Type: Resistor; Manufacturer: Panasonic - ECG; Manufacturer_Part_Number: ERJ-3GEY0R00V; Note: 13051103 = Digi No. for GE WDNU; Digi_PN: 13050568; Component_Life_Cycle_State: Reviewed; Area: 2.5; Project: Adjustable Foundation; Voltage: 75V
R5 = 1000265: RES 0.0 OHM 1/20W 0201 SMD; Part_Type: Resistor; Manufacturer: Panasonic - ECG; Manufacturer_Part_Number: ERJ-1GE0R00C; Digi_PN: 13050655; Component_Life_Cycle_State: CAD Reviewed; Area: 0.47; Project: CLC; Power_WV_SRF: 50; Tolerance: Jumper
R20 R23 = 1001158: RES 120 OHM 1/16W 1% 0402 SMD; Part_Type: Resistor; Manufacturer: Yageo; Manufacturer_Part_Number: RC0402FR-07120RL; Digi_PN: 13050832; Component_Life_Cycle_State: Reviewed; Area: 0.95; Project: CCWMX6_SBC board; Note: 13051102 = Digi No. for GE WDNU
R38 R231 R260 = 1000537: RES 10.0K OHM 1/10W 1% 0402 SMD; Part_Type: Resistor; Manufacturer: Panasonic - ECG; Manufacturer_Part_Number: ERJ-2RKF1002X; Component_Life_Cycle_State: CAD Reviewed; Area: 0.95; Project: KITT; Power_WV_SRF: 100; Digi_PN: 13051084
R42 R274 R275 = 1000076: RES 0.0 OHM 1/10W 0402 SMD; Part_Type: Resistor; Manufacturer: Panasonic - ECG; Manufacturer_Part_Number: ERJ-2GE0R00X; Component_Life_Cycle_State: Proven; Area: 0.95; Project: Adjustable Foundation; Power_WV_SRF: 10; Digi_PN: 13050387
R270-R273 R283 = 1000079: RES 1.00K OHM 1/10W 1% 0402 SMD; Part_Type: Resistor; Manufacturer: Panasonic - ECG; Manufacturer_Part_Number: ERJ-2RKF1001X; Digi_PN: 13051085; Component_Life_Cycle_State: Proven; Area: 0.95; Project: Adjustable Foundation; Power_WV_SRF: 10
SW4 = 1001500: SWITCH DIP 2POS HALF PITCH 24V; Manufacturer: C&K Components; Digi_PN: 22000060; Component_Life_Cycle_State: Reviewed; Area: 34.3; Project: CCWMX6_SBC board; Note: 22000296 = Digi No. for GE WDNU
TP1-TP5 TP8 TP16 = CAD0011: TEST POINT 30mil PAD SMT; Component_Life_Cycle_State: Reviewed; Area: 0.58; Project: CLC
U10 = 1001647: IC LOGIC GATE UNIV 2INPUT SC70-6; Manufacturer: Fairchild Semiconductor; Note: 16051964 = Digi No. for GE WDNU; Digi_PN: TI02699; Component_Life_Cycle_State: Reviewed; Area: 7; Project: WDNU-II
U11 = 1001973: ConnectCore for i.MX6UL module - LGA; Manufacturer: DIGI; Manufacturer_Part_Number: 55001875-01; Digi_PN: 50001939-01; Component_Life_Cycle_State: Reviewed; Area: 841
U36 = 1001009: MOSFET DL N-CH 60V 410MA SOT-563; Part_Type: Transistor; Manufacturer: Diodes, Inc.; Digi_PN: 17050796; Component_Life_Cycle_State: Reviewed; Area: 2,89; Project: ConnectCore i.MX6 module

## Sheet 03 - Power, boot strap, reset.SchDoc: Power, Boot
size A3; PageSetup: Record=PageOptions¦CenterHorizontal=True¦CenterVertical=True¦PrintScale=0.70¦XCorrection=1.00¦YCorrection=1.00¦PrintKind=0¦BorderSize=5000000¦LeftOffset=0¦BottomOffset=0¦Orientation=2¦PaperLength=4200¦PaperWidth=2970¦Scale=100¦PaperSource=7¦PrintQuality=600¦MediaType=1¦DitherType=10¦PaperKind=A4¦PrintScaleMode=1; Author: Sébastien MEYER; SheetNumber: 3; SheetTotal: 14
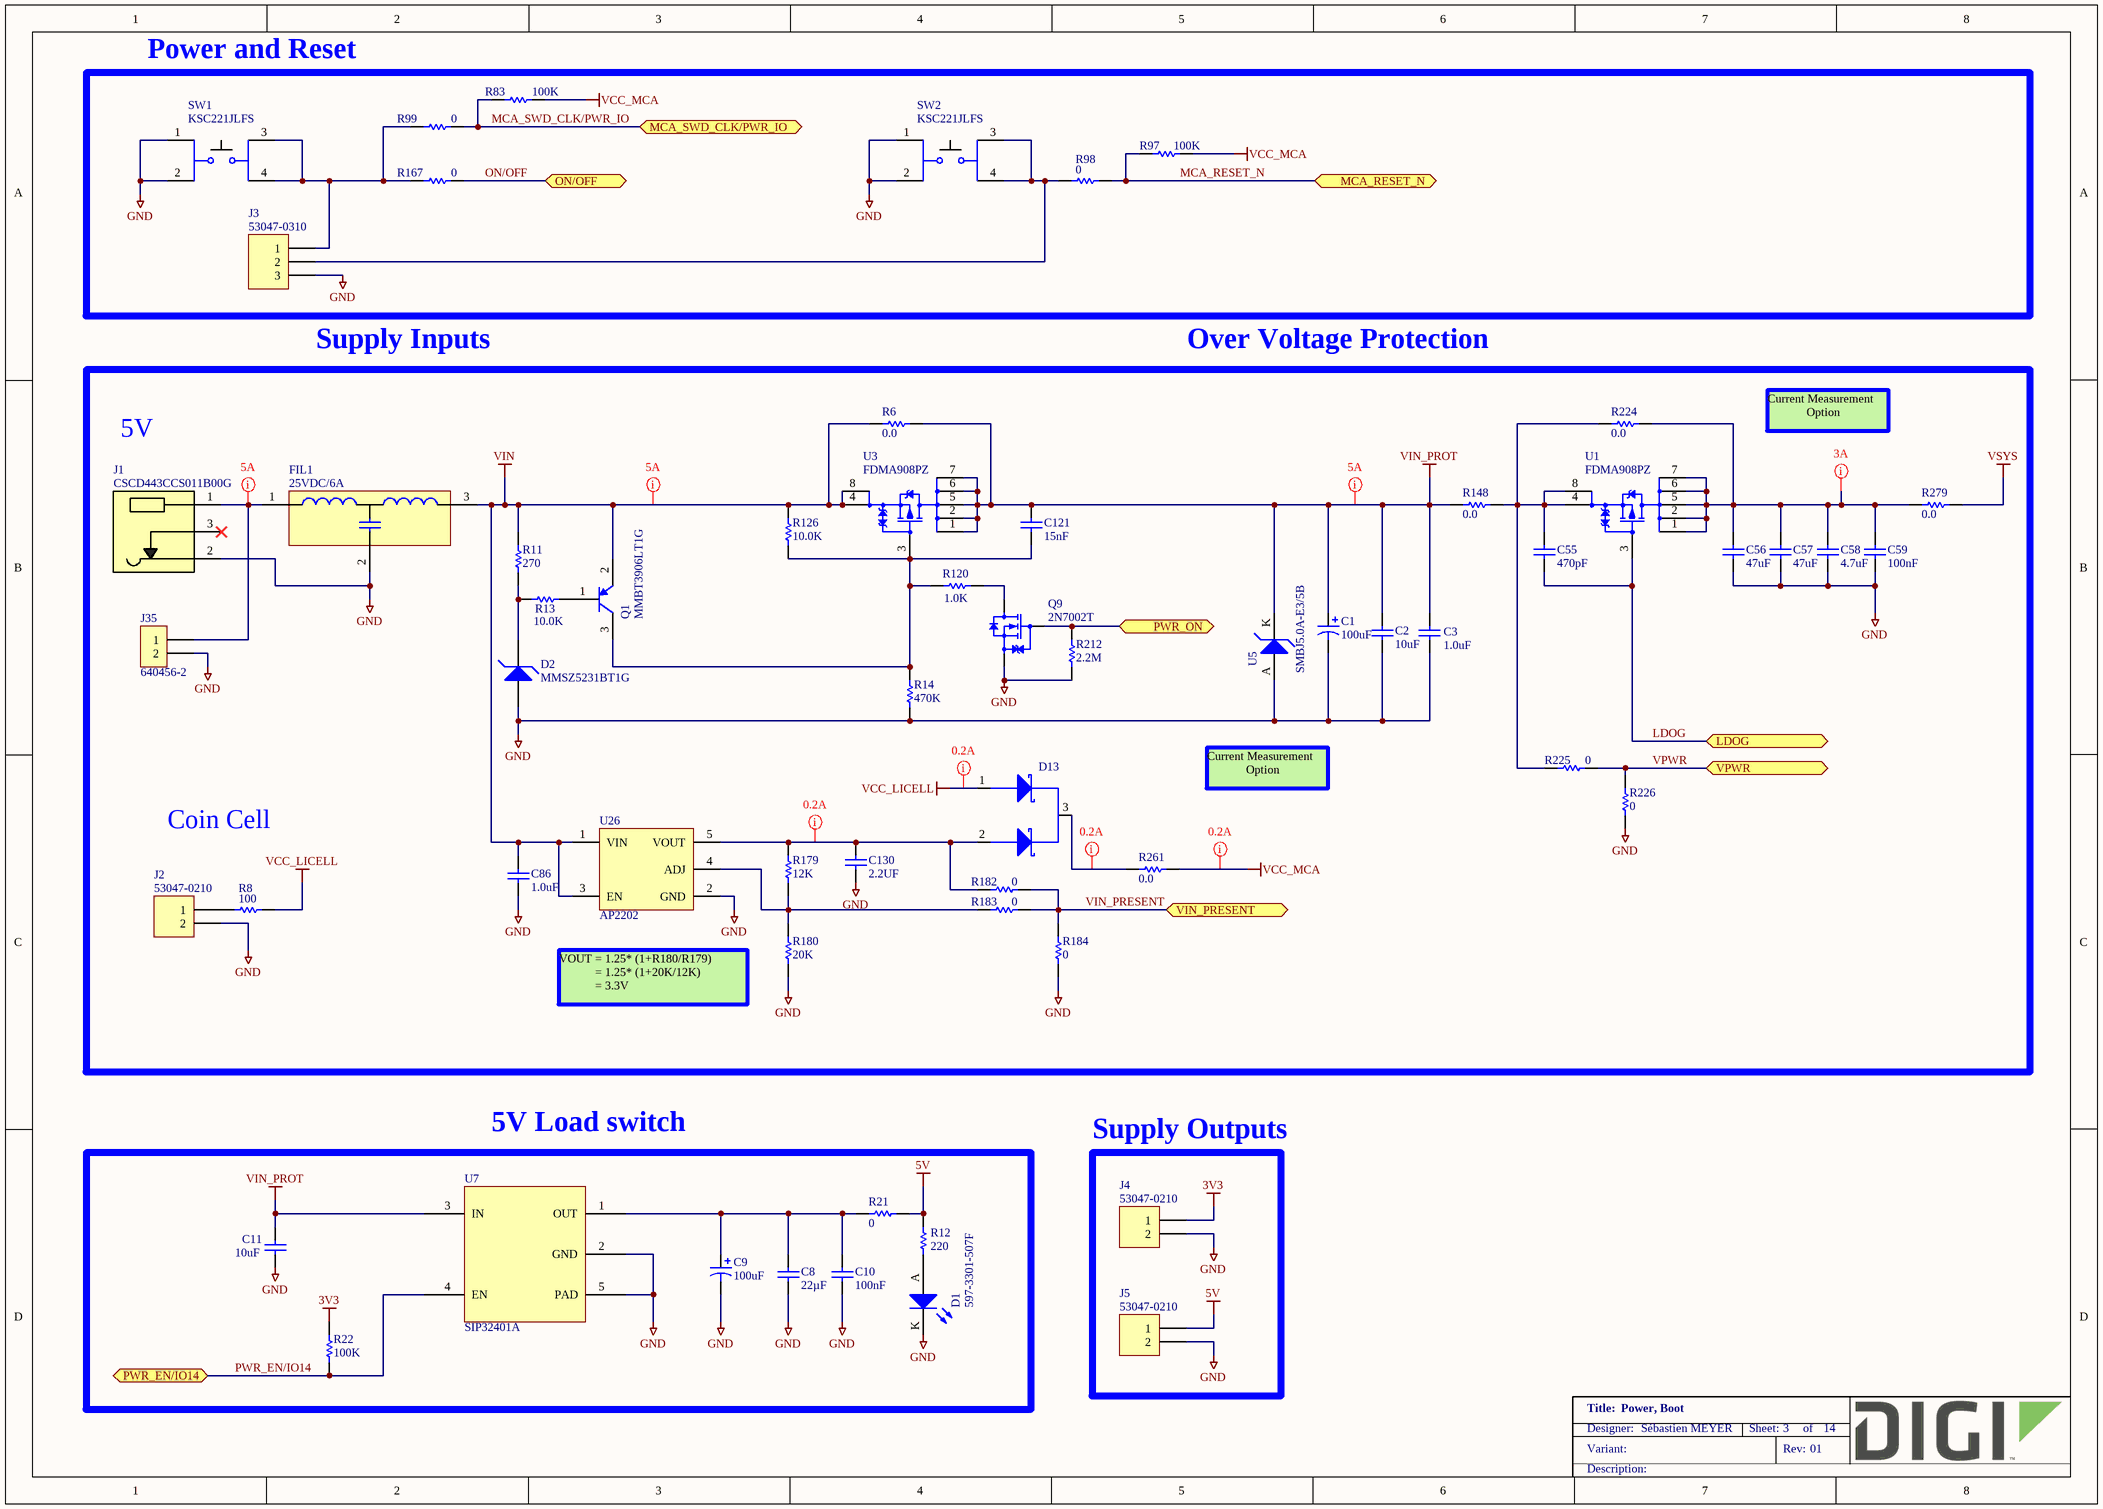
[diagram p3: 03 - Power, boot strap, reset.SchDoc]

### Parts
C1  100uF  [CAPMP3216X120N]
C2  10uF  [CAPC1005X55N]
C3  1.0uF  [CAPC1005X55N]
C8  22µF  [CAPC1608X90N]
C9  100uF  [CAPMP3216X120N]
C10  100nF  [CAPC1005X55N]
C11  10uF  [CAPC1005X55N]
C55  470pF  [CAPC1005X55N]
C56  47uF  [CAPC2013X145N]
C57  47uF  [CAPC2013X145N]
C58  4.7uF  [CAPC2013X135N]
C59  100nF  [CAPC1005X55N]
C86  1.0uF  [CAPC1005X55L]
C121  15nF  [CAPC1005X55N]
C130  2.2UF  [CAPC1608X90N]
D1  597-3301-507F  [LEDM3020X130N]
D2  MMSZ5231BT1G  [SOD3716X135N]
D13  BAT54CWT1G  [SOT65P210X100-3AN]  (value not drawn)
FIL1  25VDC/6A  [FIL_ELKEA]
J1  CSCD443CCS011B00G  [conn_CSCD443CCS011B00G]
J2  Manufacturer_Part_Number: 53047-0210  [MOLEX_53047-0210]  (hidden comment: 1x2P)
J3  Manufacturer_Part_Number: 53047-0310  [MOLEX_53047-0310]  (hidden comment: 1x3P)
J4  Manufacturer_Part_Number: 53047-0210  [MOLEX_53047-0210]  (hidden comment: 1x2P)
J5  Manufacturer_Part_Number: 53047-0210  [MOLEX_53047-0210]  (hidden comment: 1x2P)
J35  640456-2  [TE_640456-2]
Q1  MMBT3906LT1G  [SOT95P240X110-3N]
Q9  2N7002T  [SOTFL50P160X80_GSD-3N]
R6  0.0  [RESC2013X70N]
R8  100  [RESC1005X40N]
R11  270  [RESC2013X70N]
R12  220  [RESC1005X40N]
R13  10.0K  [RESC1005X40N]
R14  470K  [RESC1005X40N]
R21  0  [RESC1609X55N]
R22  100K  [RESC1005X40N]
R83  100K  [RESC1005X40N]
R97  100K  [RESC1005X40N]
R98  0  [RESC1005X40N]
R99  0  [RESC1005X40N]
R120  1.0K  [RESC1005X40N]
R126  10.0K  [RESC1005X40N]
R148  0.0  [RESC2013X70N]
R167  0  [RESC1005X40N]
R179  12K  [RESC1609X55N]
R180  20K  [RESC1609X55N]
R182  0  [RESC1005X40N]
R183  0  [RESC1005X40N]
R184  0  [RESC1005X40N]
R212  2.2M  [RESC1005X40N]
R224  0.0  [RESC2013X70N]
R225  0  [RESC1609X55N]
R226  0  [RESC1609X55N]
R261  0.0  [RESC2013X70N]
R279  0.0  [RESC2013X70N]
SW1  KSC221JLFS  [SW_KSC221J]
SW2  KSC221JLFS  [SW_KSC221J]
U1  FDMA908PZ  [DFN200X200X80-6N]
U3  FDMA908PZ  [DFN200X200X80-6N]
U5  SMBJ5.0A-E3/5B  [DIOM5436X244N]
U7  SIP32401A  [SON50P120X160X60-5T55X91N]
U26  AP2202  [SOT95P280X145-5N]

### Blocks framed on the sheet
Power and Reset: J3 R83 R97-R99 R167 SW1 SW2
5V Load switch: C8-C11 D1 R12 R21 R22 U7
Supply Outputs: J4 J5

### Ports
LDOG (bidir), MCA_RESET_N (bidir), MCA_SWD_CLK/PWR_IO (bidir), ON/OFF (bidir), PWR_EN/IO14 (bidir), PWR_ON (bidir), VIN_PRESENT (bidir), VPWR (bidir)

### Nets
3V3: J4.1 R22.1
5V: J5.1 R12.2 R21.2
GND: C1.2 C2.1 C3.1 C8.1 C9.2 C10.1 C11.1 C56.1 C57.1 C58.1 C59.1 C86.1 C130.1 D1.K D2.A FIL1.2 J1.2 J2.2 J3.3 J4.2 J5.2 J35.2 Q9.S R14.1 R180.1 R184.1 R212.1 R226.1 SW1.1 SW1.2 SW2.1 SW2.2 U5.A U7.2(GND) U7.5(PAD) U26.2(GND)
VCC_LICELL: D13.1 R8.2
VCC_MCA: R83.2 R97.2 R261.2
VIN: C86.2 FIL1.3(GND) Q1.2(E) R6.1 R11.2 R126.2 U3.4(S) U3.8(S) U26.1(VIN) U26.3(EN)
VIN_PROT: C1.1 C2.2 C3.2 C11.2 C121.1 R6.2 R148.1 U3.1(D) U3.2(D) U3.5(D) U3.6(D) U3.7(D) U5.K U7.3(IN)
VSYS: R279.2
LDOG: C55.1 U1.3(G) ; port LDOG
MCA_RESET_N: R97.1 R98.2 ; port MCA_RESET_N
MCA_SWD_CLK/PWR_IO: R83.1 R99.2 ; port MCA_SWD_CLK/PWR_IO
ON/OFF: R167.2 ; port ON/OFF
PWR_EN/IO14: R22.2 U7.4(EN) ; port PWR_EN/IO14
PWR_ON: Q9.G R212.2 ; port PWR_ON
VIN_PRESENT: R182.2 R183.2 R184.2 ; port VIN_PRESENT
VPWR: R225.2 R226.2 ; port VPWR
NetC8_2: C8.2 C9.1 C10.2 R21.1 U7.1(OUT)
NetC55_2: C55.2 R148.2 R224.1 R225.1 U1.4(S) U1.8(S)
NetC56_2: C56.2 C57.2 C58.2 C59.2 R224.2 R279.1 U1.1(D) U1.2(D) U1.5(D) U1.6(D) U1.7(D)
NetC121_2: C121.2 Q1.3(C) R14.2 R120.1 R126.1 U3.3(G)
NetC130_2: C130.2 D13.2 R179.2 R182.1 U26.5(VOUT)
NetD1_A: D1.A R12.1
NetD2_K: D2.K R11.1 R13.1
NetD13_3: D13.3 R261.1
NetFIL1_1: FIL1.1(GND) J1.1 J35.1
NetJ2_1: J2.1 R8.1
NetJ3_1: J3.1 R99.1 R167.1 SW1.3 SW1.4
NetJ3_2: J3.2 R98.1 SW2.3 SW2.4
NetQ1_1: Q1.1(B) R13.2
NetQ9_D: Q9.D R120.2
NetR179_1: R179.1 R180.2 R183.1 U26.4(ADJ)

Not connected (* = marked no-connect by the designer): J1 3*

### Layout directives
net class 3A: NetC56_2
net class 0.2A: NetC130_2, NetD13_3, VCC_LICELL, VCC_MCA
net class 5A: NetFIL1_1, VIN, VIN_PROT

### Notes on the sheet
- Supply Inputs
- Over Voltage Protection
- 5V
- Current Measurement
  Option
- Coin Cell
- VOUT = 1.25* (1+R180/R179)
  = 1.25* (1+20K/12K)
  = 3.3V

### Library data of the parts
C1 C9 = 1001196: CAP TANT 100UF 6.3V 20% 1206; Part_Type: Capacitor; Manufacturer: Rohm; Manufacturer_Part_Number: TCTAL0J107M8R; Digi_PN: 14050490; Component_Life_Cycle_State: Reviewed; Area: 8.01; Project: CCWMX6_SBC board
C2 C11 = 1001168: CAP CER 10UF 10V 20% X5R 0402; Part_Type: Capacitor; Manufacturer: Samsung; Manufacturer_Part_Number: CL05A106MP5NUNC; Digi_PN: 14050689; Component_Life_Cycle_State: Reviewed; Area: 0.95; Project: CCWMX6_SBC board
C3 = 1001167: CAP CER 1UF 10V 10% X5R 0402; Part_Type: Capacitor; Manufacturer: Murata; Manufacturer_Part_Number: GRM155R61A105KE15D; Digi_PN: 14050399; Component_Life_Cycle_State: Reviewed; Area: 0.95; Project: CCWMX6_SBC board
C8 = 1000998: CAP CER 22UF 10V 20% X5R 0603; Part_Type: Capacitor; Manufacturer: Samsung; Manufacturer_Part_Number: CL10A226MP8NUNE; Manufacturer_Alt_1: TDK Corporation; Manufacturer_Alt_1_Part_Number: C1608X5R1A226M080AC; Digi_PN: 14050684; Component_Life_Cycle_State: Reviewed; Area: 2.27; Project: ConnectCore i.MX6 module; Tolerance: 20
C10 C59 = 1000006: as C150 on sheet 02 - CCIMX6UL Module
C55 = 1001576: CAP CER 470PF 50V 5% NP0 0402; Part_Type: Capacitor; Manufacturer: Murata; Manufacturer_Part_Number: GRM1555C1H471JA01J; Digi_PN: 14050366; Component_Life_Cycle_State: Reviewed; Area: 0,95; Project: WDNU-II; Tolerance: +/- 5%
C56 C57 = 1000501: CAP CER 47UF 6.3V 20% X5R 0805; Part_Type: Capacitor; Manufacturer: Taiyo Yuden; Manufacturer_Part_Number: JMK212BJ476MG-T; Digi_PN: 14050627; Component_Life_Cycle_State: Reviewed; Area: 6.4; Project: SDR Prototype RF Board
C58 = 1000500: CAP CER 4.7UF 25V 10% X5R 0805; Part_Type: Capacitor; Manufacturer: Murata; Manufacturer_Part_Number: GRM21BR61E475KA12L; Component_Life_Cycle_State: Reviewed; Area: 4.24; Project: SDR Prototype RF Board; Digi_PN: 14050307
C86 = 1000073: CAP CER 1UF 6.3V 20% X5R 0402; Part_Type: Capacitor; Manufacturer: Murata; Manufacturer_Part_Number: GRM155R60J105ME19D; Digi_PN: 14050543; Component_Life_Cycle_State: Proven; Area: 0.95; Project: Adjustable Foundation
C121 = 1000512: CAP CER 0.015UF 16V 10% X7R 0402; Part_Type: Capacitor; Manufacturer: Murata; Manufacturer_Part_Number: GRM155R71C153KA01D; Digi_PN: 14050713; Component_Life_Cycle_State: CAD Reviewed; Area: 0.95; Project: Cellular Proof of Concept
C130 = 1001303: CAP CER 2.2UF 16V 10% X5R 0603; Part_Type: Capacitor; Manufacturer: TDK Corporation; Manufacturer_Part_Number: C1608X5R1C225K080AB; Digi_PN: 14050730; Component_Life_Cycle_State: Reviewed; Area: 2,27; Project: Pinnacle
D1 = 1001189: as D3 on sheet 02 - CCIMX6UL Module
D2 = 1001494: DIODE ZENER 5.1V 500MW SOD123; Part_Type: Diodes; Manufacturer: On Semiconductor; Digi_PN: 17050700; Component_Life_Cycle_State: Reviewed; Area: 8.28; Project: CCWMX6_SBC board; Note: 17050805 = Digi No. for GE WDNU
D13 = 1000794: DIODE SCHOTTKY 30V 200MA SOT323; Part Number: SDS1920004; Manufacturer: Fairchild Semiconductor; Manufacturer Alt 1: none; Manufacturer Part Num: 0082610201; Part_Type: Diodes; Digi_PN: 17050561; Component_Life_Cycle_State: CAD Reviewed; Area: 7,68; Project: SmartMeter2
FIL1 = 1001918: DNF 2 MHZ -1000 MHZ SMD; Part_Type: Filter; Manufacturer: Panasonic - ECG; Manufacturer_Part_Number: ELKEA333FA; Digi_PN: 21000532; Component_Life_Cycle_State: Reviewed; Area: 22; Project: CCWMX6_SBC board
J1 = 1001105: DC Power Jack; Part_Type: Connector; Manufacturer: Bobbintron Electrical Corp; Digi_PN: 18000302; Component_Life_Cycle_State: Reviewed; Area: 137; Project: CCWMX6_SBC board
J2 J4 J5 = 1001136: CONN HEADER 2POS 1.25MM VERT TIN; Part_Type: Connector; Manufacturer: Molex; Component_Life_Cycle_State: Reviewed; Area: 13.6; Project: CCWMX6_SBC board; Digi_PN: 18050343
J3 = 1001183: CONN HEADER 3POS 1.25MM VERT TIN; Part_Type: Connector; Manufacturer: Molex; Digi_PN: 18050349; Component_Life_Cycle_State: Reviewed; Area: 17.6; Project: CCWMX6_SBC board
J35 = 1002003: CONN HEADER VERT 2POS .100 TIN; Part_Type: Connector; Manufacturer: TE Connectivity; Digi_PN: 18050128; Component_Life_Cycle_State: Created; Area: 29,05; Project: iMX6UL+PMIC
Q1 = 1001204: TRANS GP SS PNP 40V SOT23; Part_Type: IC; Manufacturer: On Semiconductor; Digi_PN: 17050145; Component_Life_Cycle_State: Reviewed; Area: 10.92; Project: CCWMX6_SBC board
Q9 = 1000715: MOSFET N-CH 60V 115MA SOT-523F; Part_Type: Transistor; Manufacturer: Fairchild Semiconductor; Note: 17050841 = Digi No. for GE WDNU; Digi_PN: 17050797; Component_Life_Cycle_State: CAD Reviewed; Area: 3,06; Project: SmartMeter2
R6 R148 R224 R261 R279 = 1001557: RES 0.0 OHM 1/8W JUMP 0805 SMD; Part_Type: Resistor; Manufacturer: Yageo; Manufacturer_Part_Number: RC0805JR-070RL; Note: 13051095 = Digi No. for GE WDNU; Digi_PN: TR00037; Component_Life_Cycle_State: Reviewed; Area: 5.8; Project: WDNU-II; Power_WV_SRF: 125
R8 = 1000467: RES 100 OHM 1/10W 1% 0402 SMD; Part_Type: Resistor; Manufacturer: Panasonic - ECG; Manufacturer_Part_Number: ERJ-2RKF1000X; Component_Life_Cycle_State: CAD Reviewed; Area: 0.95; Project: KITT; Digi_PN: 13051087
R11 = 1001323: RES 270 OHM 1/2W 5% 0805 SMD; Part_Type: Resistor; Manufacturer: Panasonic - ECG; Manufacturer_Part_Number: ERJ-P06J271V; Digi_PN: 13051049; Component_Life_Cycle_State: Reviewed; Area: 4.12; Project: Pinnacle; Power_WV_SRF: 500
R12 = 1001154: RES 220 OHM 1/16W 1% 0402 SMD; Part_Type: Resistor; Manufacturer: Yageo; Manufacturer_Part_Number: RC0402FR-07220RL; Digi_PN: 13050623; Component_Life_Cycle_State: Reviewed; Area: 0.95; Project: CCWMX6_SBC board
R13 R126 = 1000537: RES 10.0K OHM 1/10W 1% 0402 SMD; Part_Type: Resistor; Manufacturer: Panasonic - ECG; Manufacturer_Part_Number: ERJ-2RKF1002X; Digi_PN: 13051084; Component_Life_Cycle_State: CAD Reviewed; Area: 0.95; Project: KITT; Power_WV_SRF: 100
R14 = 1000701: RES 470K OHM 1/10W 1% 0402 SMD; Part_Type: Resistor; Manufacturer: Panasonic - ECG; Manufacturer_Part_Number: ERJ-2RKF4703X; Component_Life_Cycle_State: CAD Reviewed; Area: 0.95; Project: KITT; Power_WV_SRF: 100; Digi_PN: 13051092
R21 R225 R226 = 1000208: as R1 on sheet 02 - CCIMX6UL Module
R22 = 1000480: RES 100K OHM 1/10W 1% 0402 SMD; Part_Type: Resistor; Manufacturer: Panasonic - ECG; Manufacturer_Part_Number: ERJ-2RKF1003X; Digi_PN: 13051063; Component_Life_Cycle_State: CAD Reviewed; Area: 0.95; Project: KITT; Power_WV_SRF: 100
R83 R97 = 1000480: RES 100K OHM 1/10W 1% 0402 SMD; Part_Type: Resistor; Manufacturer: Panasonic - ECG; Manufacturer_Part_Number: ERJ-2RKF1003X; Digi_PN: 13051063; Component_Life_Cycle_State: CAD Reviewed; Area: 0,95; Project: KITT; Power_WV_SRF: 100
R98 R99 R167 R182-R184 = 1000076: as R42 on sheet 02 - CCIMX6UL Module
R120 = 1000079: as R270 on sheet 02 - CCIMX6UL Module
R179 = 1001200: RES 12.0K OHM 1/10W 1% 0603 SMD; Part_Type: Resistor; Manufacturer: Yageo; Manufacturer_Part_Number: RC0603FR-0712KL; Digi_PN: 13050531; Component_Life_Cycle_State: Reviewed; Area: 2,5; Project: LuCoV2; Power_WV_SRF: 100; Tolerance: 1
R180 = 1000142: RES 20K OHM 1/10W 5% 0603 SMD; Part_Type: Resistor; Manufacturer: Panasonic - ECG; Manufacturer_Part_Number: ERJ-3GEYJ203V; Digi_PN: 13050013; Component_Life_Cycle_State: Reviewed; Area: 2,5; Project: Adjustable Foundation; Power_WV_SRF: 100; Tolerance: 5
R212 = 1001917: RES SMD 2.2M OHM 5% 1/10W 0402; Part_Type: Resistor; Manufacturer: Panasonic - ECG; Manufacturer_Part_Number: ERJ-2GEJ225X; Digi_PN: 13050820; Component_Life_Cycle_State: Reviewed; Area: 2,27; Project: Powerley Energy Bridge; Power_WV_SRF: 0,1
SW1 SW2 = 1001124: SWITCH TACTILE SPST-NO 0.05A 32V; Manufacturer: ITT; Digi_PN: 22000059; Component_Life_Cycle_State: Reviewed; Area: 37; Project: CCWMX6_SBC board; Note: 22000295 = Digi No. for GE WDNU
U1 U3 = 1001972: MOSFET P-CH 12V 12A 6QFN; Part_Type: Transistor; Manufacturer: Fairchild Semiconductors; Digi_PN: 17050873; Component_Life_Cycle_State: Created; Area: 4; Project: iMX6UL+PMIC
U5 = 1001206: TVS DIODE 5VWM 9.2VC SMB; Part_Type: Circuit Protection; Manufacturer: Vishay Semiconductors; Digi_PN: 17050018; Component_Life_Cycle_State: Reviewed; Area: 22.4; Project: CCWMX6_SBC board
U7 = 1001857: IC SW W/CTRL SLEW RATE 4TDFN; Manufacturer: Vishay Siliconix; Manufacturer_Part_Number: SIP32401ADNP-T1GE4; Component_Life_Cycle_State: Reviewed; Area: 4.93; Project: CCWMX6_SBC board; Digi_PN: 16052004
U26 = 1001979: IC REG LDO ADJ 0.15A SOT25; Part_Type: Regulator; Manufacturer: Diodes, Inc.; Manufacturer_Part_Number: AP2202K-ADJTRG1; Digi_PN: 17050874; Component_Life_Cycle_State: Created; Area: 8,9; Project: iMX6UL+PMIC

## Sheet 04 - MicroSD, eMMC, Mini PCIe, microSIM.SchDoc: MicroSD/eMMC, Mini PCIe, MicroSIM
size A3; PageSetup: Record=PageOptions¦CenterHorizontal=True¦CenterVertical=True¦PrintScale=0.70¦XCorrection=1.00¦YCorrection=1.00¦PrintKind=0¦BorderSize=5000000¦LeftOffset=0¦BottomOffset=0¦Orientation=2¦PaperLength=4200¦PaperWidth=2970¦Scale=100¦PaperSource=7¦PrintQuality=600¦MediaType=1¦DitherType=10¦PaperKind=A4¦PrintScaleMode=1; Author: Sébastien MEYER; SheetNumber: 4; SheetTotal: 14
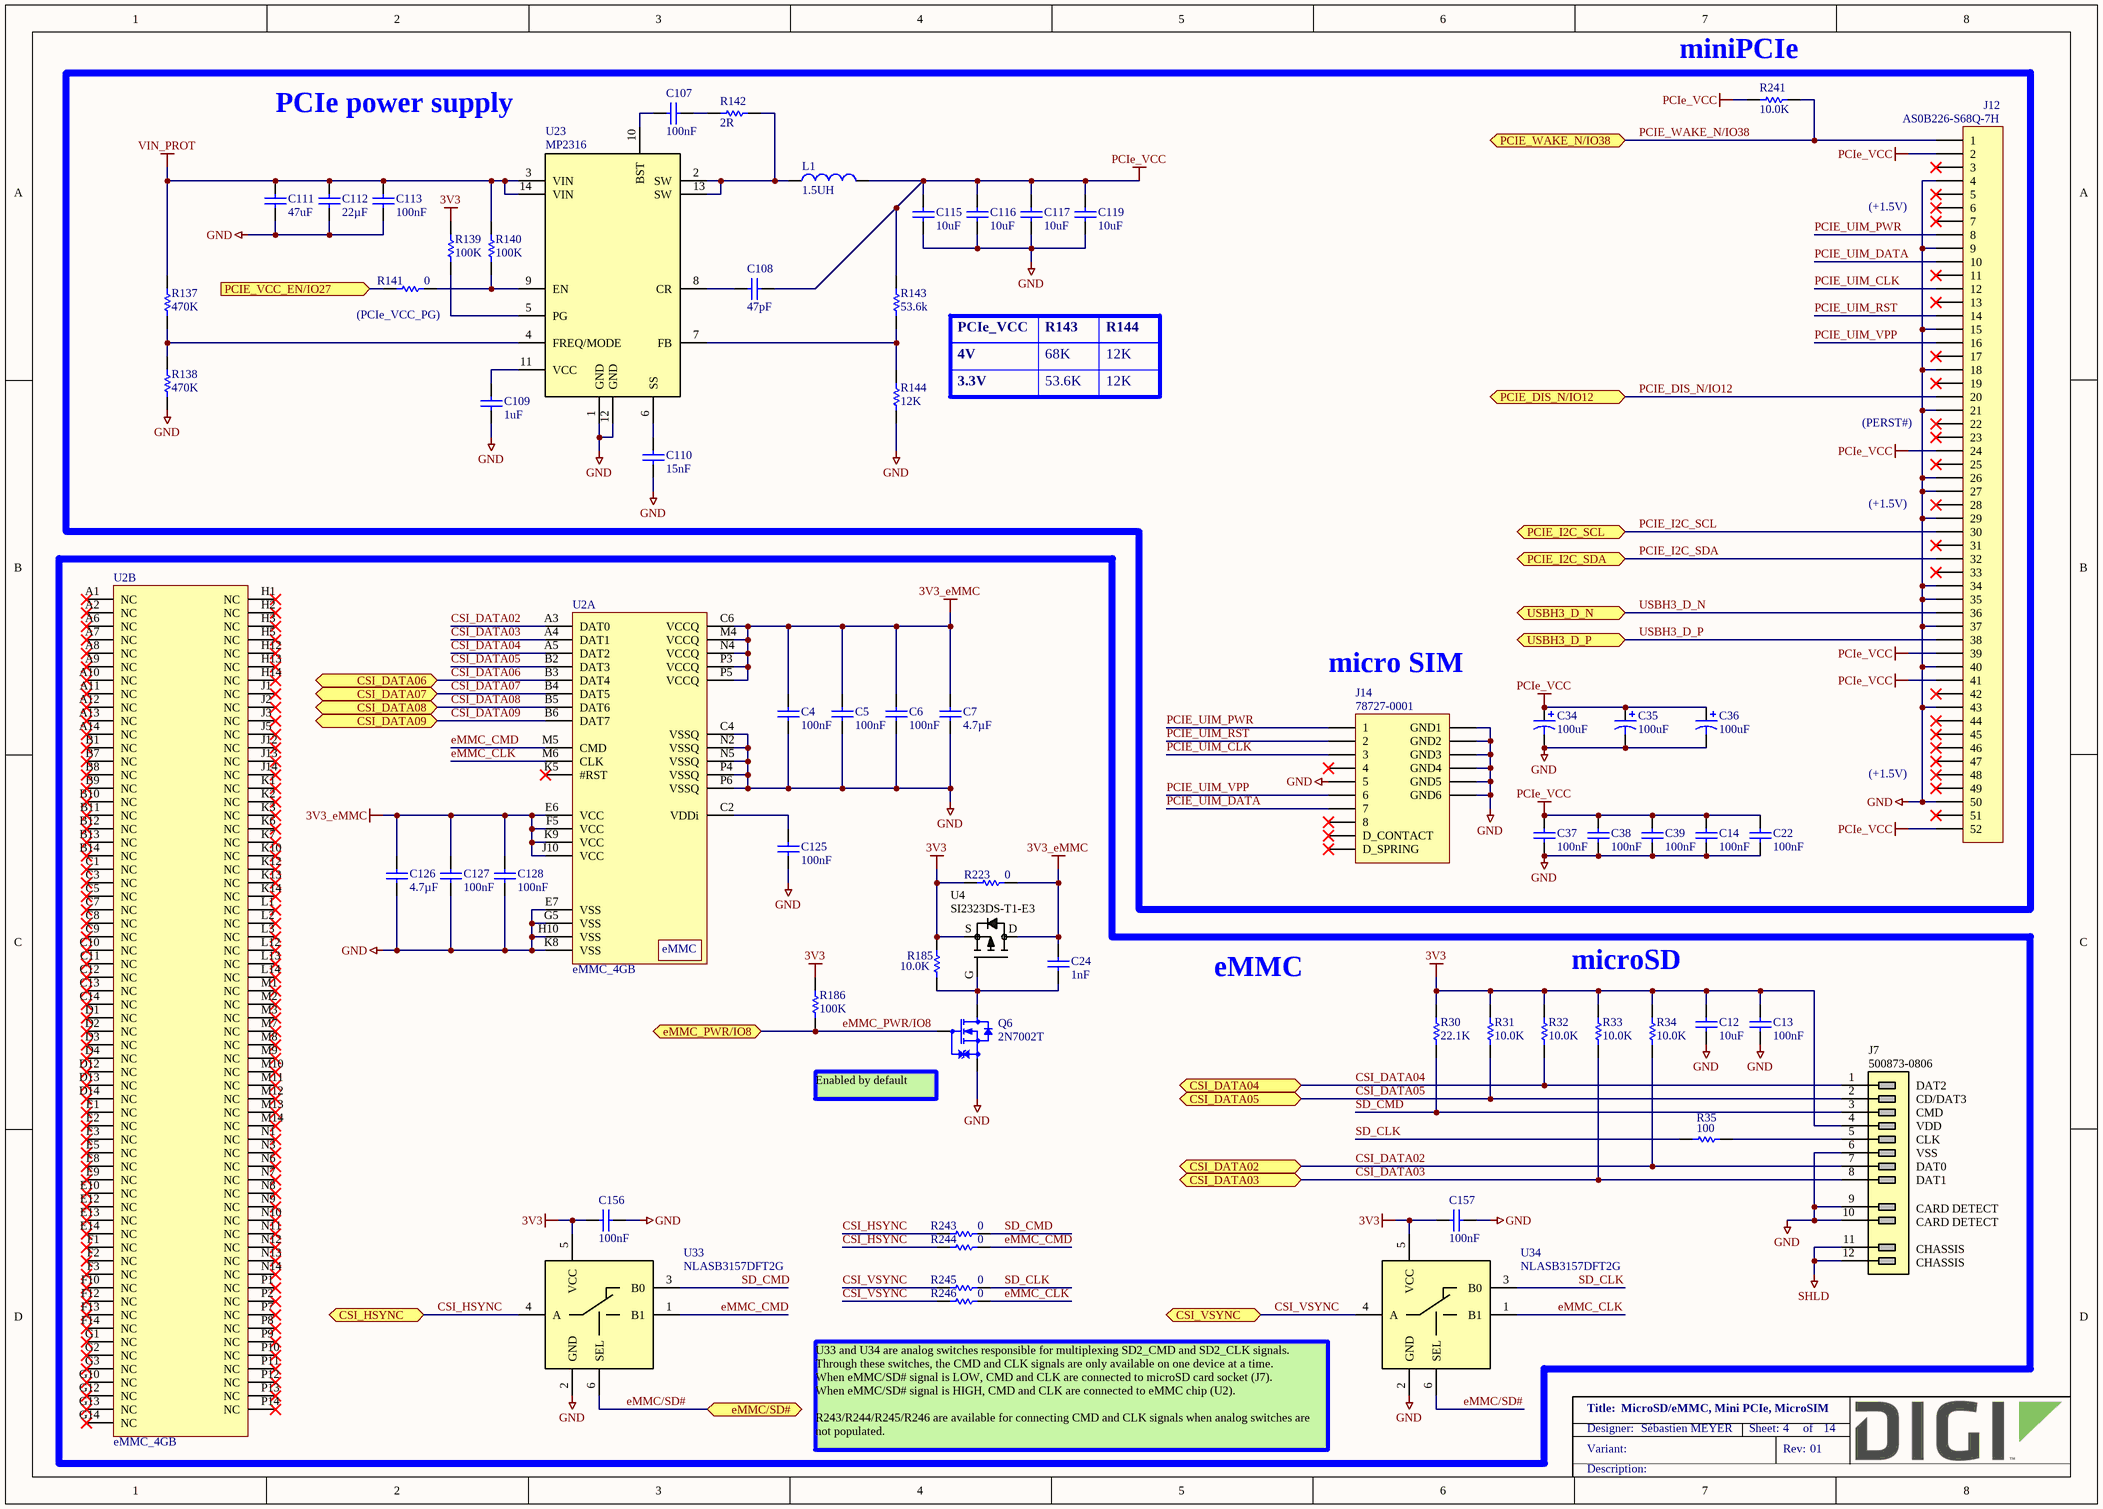
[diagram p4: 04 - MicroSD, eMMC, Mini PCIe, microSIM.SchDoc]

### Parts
C4  100nF  [CAPC1005X55N]
C5  100nF  [CAPC1005X55N]
C6  100nF  [CAPC1005X55N]
C7  4.7µF  [CAPC1005X55AL]
C12  10uF  [CAPC1005X55N]
C13  100nF  [CAPC1005X55N]
C14  100nF  [CAPC1005X55N]
C22  100nF  [CAPC1005X55N]
C24  1nF  [CAPC1005X55N]
C34  100uF  [CAPMP3216X120N]
C35  100uF  [CAPMP3216X120N]
C36  100uF  [CAPMP3216X120N]
C37  100nF  [CAPC1005X55N]
C38  100nF  [CAPC1005X55N]
C39  100nF  [CAPC1005X55N]
C107  100nF  [CAPC1005X55N]
C108  47pF  [CAPC1005X55N]
C109  1uF  [CAPC1608X90N]
C110  15nF  [CAPC1005X55N]
C111  47uF  [CAPC2013X145N]
C112  22µF  [CAPC1608X90N]
C113  100nF  [CAPC1005X55N]
C115  10uF  [CAPC2013X135N]
C116  10uF  [CAPC2013X135N]
C117  10uF  [CAPC2013X135N]
C119  10uF  [CAPC2013X135N]
C125  100nF  [CAPC1005X55N]
C126  4.7µF  [CAPC1005X55AL]
C127  100nF  [CAPC1005X55N]
C128  100nF  [CAPC1005X55N]
C156  100nF  [CAPC1005X55N]
C157  100nF  [CAPC1005X55N]
J7  500873-0806  [MOLEX_500873-0806]
J12  Manufacturer_Part_Number: AS0B226-S68Q-7H  [FOXCONN_AS0B221-S68Q-7H]  (hidden comment: PCIe Minicard)
J14  78727-0001  [MOLEX_78727-0001]
L1  1.5UH  [INDM_SRP4020TA]
Q6  2N7002T  [SOTFL50P160X80_GSD-3N]
R30  22.1K  [RESC1005X40N]
R31  10.0K  [RESC1005X40N]
R32  10.0K  [RESC1005X40N]
R33  10.0K  [RESC1005X40N]
R34  10.0K  [RESC1005X40N]
R35  100  [RESC1005X40N]
R137  470K  [RESC1005X40N]
R138  470K  [RESC1005X40N]
R139  100K  [RESC1005X40N]
R140  100K  [RESC1005X40N]
R141  0  [RESC1005X40N]
R142  2R  [RESC1609X55N]
R143  53.6k  [RESC1609X55N]
R144  12K  [RESC1609X55N]
R185  10.0K  [RESC1005X40N]
R186  100K  [RESC1005X40N]
R223  0  [RESC1609X55N]
R241  10.0K  [RESC1005X40N]
R243  0  [RESC1005X40N]
R244  0  [RESC1005X40N]
R245  0  [RESC1005X40N]
R246  0  [RESC1005X40N]
U2  eMMC_4GB  [BGA153C50P14X14_1150X1300X100]  (parts A,B of 2)
U4  SI2323DS-T1-E3  [SOT95P240X110_GSD-3N]
U23  MP2316  [QFN_MPS_MP2316]
U33  NLASB3157DFT2G  [SOT65P210X110-6N]
U34  NLASB3157DFT2G  [SOT65P210X110-6N]

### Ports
CSI_DATA02 (bidir), CSI_DATA03 (bidir), CSI_DATA04 (bidir), CSI_DATA05 (bidir), CSI_DATA06 (bidir), CSI_DATA07 (bidir), CSI_DATA08 (bidir), CSI_DATA09 (bidir), CSI_HSYNC (bidir), CSI_VSYNC (bidir), eMMC/SD# (bidir), eMMC_PWR/IO8 (bidir), PCIE_DIS_N/IO12 (bidir), PCIE_I2C_SCL (bidir), PCIE_I2C_SDA (bidir), PCIE_VCC_EN/IO27 (in), PCIE_WAKE_N/IO38 (bidir), USBH3_D_N (bidir), USBH3_D_P (bidir)

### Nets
3V3: C12.2 C13.2 C156.2 C157.2 J7.4 R30.2 R31.2 R32.2 R33.2 R34.2 R139.1 R185.1 R186.1 R223.1 U4.S U33.5(VCC) U34.5(VCC)
3V3_eMMC: C4.2 C5.2 C6.2 C7.2 C24.2 C126.2 C127.2 C128.2 R223.2 U2.C6(VCCQ) U2.E6(VCC) U2.F5(VCC) U2.J10(VCC) U2.K9(VCC) U2.M4(VCCQ) U2.N4(VCCQ) U2.P3(VCCQ) U2.P5(VCCQ) U4.D
GND: C4.1 C5.1 C6.1 C7.1 C12.1 C13.1 C14.1 C22.1 C34.2 C35.2 C36.2 C37.1 C38.1 C39.1 C109.1 C110.1 C111.1 C112.1 C113.1 C115.1 C116.1 C117.1 C119.1 C125.1 C126.1 C127.1 C128.1 C156.1 C157.1 J7.6 J7.9 J7.10 J12.4 J12.9 J12.15 J12.18 J12.21 J12.26 J12.27 J12.29 J12.34 J12.35 J12.37 J12.40 J12.43 J12.50 J14.5 J14.11(GND1) J14.12(GND2) J14.13(GND3) J14.14(GND4) J14.15(GND5) J14.16(GND6) Q6.S R138.1 R144.1 U2.C4(VSSQ) U2.E7(VSS) U2.G5(VSS) U2.H10(VSS) U2.K8(VSS) U2.N2(VSSQ) U2.N5(VSSQ) U2.P4(VSSQ) U2.P6(VSSQ) U23.1(GND) U23.12(GND) U33.2(GND) U34.2(GND)
PCIe_VCC: C14.2 C22.2 C34.1 C35.1 C36.1 C37.2 C38.2 C39.2 C108.2 C115.2 C116.2 C117.2 C119.2 J12.2 J12.24 J12.39 J12.41 J12.52 L1.2 R143.2 R241.2
SHLD: J7.11 J7.12
VIN_PROT: C111.2 C112.2 C113.2 R137.2 R140.2 U23.3(VIN) U23.14(VIN)
CSI_DATA02: J7.7 R34.1 U2.A3(DAT0) ; port CSI_DATA02
CSI_DATA03: J7.8 R33.1 U2.A4(DAT1) ; port CSI_DATA03
CSI_DATA04: J7.1 R32.1 U2.A5(DAT2) ; port CSI_DATA04
CSI_DATA05: J7.2 R31.1 U2.B2(DAT3) ; port CSI_DATA05
CSI_DATA06: U2.B3(DAT4) ; port CSI_DATA06
CSI_DATA07: U2.B4(DAT5) ; port CSI_DATA07
CSI_DATA08: U2.B5(DAT6) ; port CSI_DATA08
CSI_DATA09: U2.B6(DAT7) ; port CSI_DATA09
CSI_HSYNC: R243.1 R244.1 U33.4(A) ; port CSI_HSYNC
CSI_VSYNC: R245.1 R246.1 U34.4(A) ; port CSI_VSYNC
eMMC/SD#: U33.6(SEL) U34.6(SEL) ; port eMMC/SD#
eMMC_CLK: R246.2 U2.M6(CLK) U34.1(B1)
eMMC_CMD: R244.2 U2.M5(CMD) U33.1(B1)
eMMC_PWR/IO8: Q6.G R186.2 ; port eMMC_PWR/IO8
PCIE_DIS_N/IO12: J12.20 ; port PCIE_DIS_N/IO12
PCIE_I2C_SCL: J12.30 ; port PCIE_I2C_SCL
PCIE_I2C_SDA: J12.32 ; port PCIE_I2C_SDA
PCIE_UIM_CLK: J12.12 J14.3
PCIE_UIM_DATA: J12.10 J14.7
PCIE_UIM_PWR: J12.8 J14.1
PCIE_UIM_RST: J12.14 J14.2
PCIE_UIM_VPP: J12.16 J14.6
PCIE_VCC_EN/IO27: R141.1 ; port PCIE_VCC_EN/IO27
PCIE_WAKE_N/IO38: J12.1 R241.1 ; port PCIE_WAKE_N/IO38
SD_CLK: R35.1 R245.2 U34.3(B0)
SD_CMD: J7.3 R30.1 R243.2 U33.3(B0)
USBH3_D_N: J12.36 ; port USBH3_D_N
USBH3_D_P: J12.38 ; port USBH3_D_P
NetC24_1: C24.1 Q6.D R185.2 U4.G
NetC107_1: C107.1 U23.10(BST)
NetC107_2: C107.2 R142.1
NetC108_1: C108.1 U23.8(CR)
NetC109_2: C109.2 U23.11(VCC)
NetC110_2: C110.2 U23.6(SS)
NetC125_2: C125.2 U2.C2(VDDi)
NetJ7_5: J7.5 R35.2
NetL1_1: L1.1 R142.2 U23.2(SW) U23.13(SW)
NetR137_1: R137.1 R138.2 U23.4(FREQ/MODE)
NetR139_2: R139.2 U23.5(PG)
NetR140_1: R140.1 R141.2 U23.9(EN)
NetR143_1: R143.1 R144.2 U23.7(FB)

Not connected (* = marked no-connect by the designer): J12 3* 5* 6* 7* 11* 13* 17* 19* 22* 23* 25* 28* 31* 33* 42* 44* 45* 46* 47* 48* 49* 51*; J14 4* 8* 9(D_CONTACT)* 10(D_SPRING)*; U2 A1(NC)* A2(NC)* A6(NC)* A7(NC)* A8(NC)* A9(NC)* A10(NC)* A11(NC)* A12(NC)* A13(NC)* A14(NC)* B1(NC)* B7(NC)* B8(NC)* B9(NC)* B10(NC)* B11(NC)* B12(NC)* B13(NC)* B14(NC)* C1(NC)* C3(NC)* C5(NC)* C7(NC)* C8(NC)* C9(NC)* C10(NC)* C11(NC)* C12(NC)* C13(NC)* C14(NC)* D1(NC)* D2(NC)* D3(NC)* D4(NC)* D12(NC)* D13(NC)* D14(NC)* E1(NC)* E2(NC)* E3(NC)* E5(NC)* E8(NC)* E9(NC)* E10(NC)* E12(NC)* E13(NC)* E14(NC)* F1(NC)* F2(NC)* F3(NC)* F10(NC)* F12(NC)* F13(NC)* F14(NC)* G1(NC)* G2(NC)* G3(NC)* G10(NC)* G12(NC)* G13(NC)* G14(NC)* H1(NC)* H2(NC)* H3(NC)* H5(NC)* H12(NC)* H13(NC)* H14(NC)* J1(NC)* J2(NC)* J3(NC)* J5(NC)* J12(NC)* J13(NC)* J14(NC)* K1(NC)* K2(NC)* K3(NC)* K5(#RST)* K6(NC)* K7(NC)* K10(NC)* K12(NC)* K13(NC)* K14(NC)* L1(NC)* L2(NC)* L3(NC)* L12(NC)* L13(NC)* L14(NC)* M1(NC)* M2(NC)* M3(NC)* M7(NC)* M8(NC)* M9(NC)* M10(NC)* M11(NC)* M12(NC)* M13(NC)* M14(NC)* N1(NC)* N3(NC)* N6(NC)* N7(NC)* N8(NC)* N9(NC)* N10(NC)* N11(NC)* N12(NC)* N13(NC)* N14(NC)* P1(NC)* P2(NC)* P7(NC)* P8(NC)* P9(NC)* P10(NC)* P11(NC)* P12(NC)* P13(NC)* P14(NC)*

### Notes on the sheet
- (near R241) miniPCIe
- (near U23) PCIe power supply
- (near J12) (+1.5V)
- (near R141) (PCIe_VCC_PG)
- PCIe_VCC
- 4V
- R143
- 68K
- R144
- 12K
- 3.3V
- 53.6K
- (near J12) (PERST#)
- (near J14) micro SIM
- eMMC
- microSD
- (near Q6) Enabled by default
- U33 and U34 are analog switches responsible for multiplexing SD2_CMD and SD2_CLK signals. Through these switches, the CMD and CLK signals are only available on one device at a time.
  When eMMC/SD# signal is LOW, CMD and CLK are connected to microSD card socket (J7).
  When eMMC/SD# signal is HIGH, CMD and CLK are connected to eMMC chip (U2).
  R243/R244/R245/R246 are available for connecting CMD and CLK signals when analog switches are not populated.

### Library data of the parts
C4-C6 C13 C14 C22 C37-C39 C125 C127 C128 C156 C157 = 1000006: as C150 on sheet 02 - CCIMX6UL Module
C7 C126 = 1000972: CAP CER 4.7UF 6.3V 20% X5R 0402; Part_Type: Capacitor; Manufacturer: Taiyo Yuden; Manufacturer_Part_Number: JMK105BBJ475MV-F; Digi_PN: 14050682; Component_Life_Cycle_State: Reviewed; Area: 0.5; Project: ConnectCore i.MX6 module; Voltage: 6.3; Tolerance: 20
C12 = 1001168: as C2 on sheet 03 - Power, boot strap, reset
C24 = 1000067: CAP CER 1000PF 50V 10% X7R 0402; Part_Type: Capacitor; Manufacturer: Murata; Manufacturer_Part_Number: GRM155R71H102KA01D; Digi_PN: 14050737; Component_Life_Cycle_State: Proven; Area: 0,95; Project: Adjustable Foundation
C34-C36 = 1001196: as C1 on sheet 03 - Power, boot strap, reset
C107 = 1000006: CAP 100nF 16V 10% X7R 0402; Part_Type: Capacitor; Manufacturer: Murata; Manufacturer_Part_Number: GRM155R71C104KA88D; Digi_PN: 14050552; Component_Life_Cycle_State: CAD Reviewed; Area: 0.95; Project: KITT; Tolerance: 10
C108 = 1000007: CAP 47pF 50V 5% NP0 0402; Part_Type: Capacitor; Manufacturer: Murata; Manufacturer_Part_Number: GRM1555C1H470JA01D; Manufacturer_Alt_1: AVX Corporation; Manufacturer_Alt_1_Part_Number: 04025A470JAT2A; Note: 14050747 is Digi No. for GE WDNU; Digi_PN: 14050309; Component_Life_Cycle_State: CAD Reviewed; Area: 0.95; Project: KITT; Temp_Coef: C0G, NP0
C109 = 1000110: CAP CER 1UF 25V 10% X5R 0603; Part_Type: Capacitor; Manufacturer: Murata; Manufacturer_Part_Number: GRM188R61E105KA12D; Manufacturer_Alt_1: AVX Corporation; Manufacturer_Alt_1_Part_Number: TMK107BJ105KA-T; Note: 14050758  = Digi No. for GE WDNU; Digi_PN: 14050618; Component_Life_Cycle_State: Reviewed; Area: 2.27; Project: Adjustable Foundation
C110 = 1000512: as C121 on sheet 03 - Power, boot strap, reset
C111 = 1000501: as C56 on sheet 03 - Power, boot strap, reset
C112 = 1000998: as C8 on sheet 03 - Power, boot strap, reset
C113 = 1000918: CAP CER 0.1UF 50V 10% X7R 0402; Part_Type: Capacitor; Manufacturer: TDK Corporation; Manufacturer_Part_Number: C1005X7R1H104K050BB; Digi_PN: 14050715; Component_Life_Cycle_State: Reviewed; Area: 0.95; Project: DTM3.0
C115-C117 C119 = 1000111: CAP CER 10UF 16V 10% X5R 0805; Part_Type: Capacitor; Manufacturer: Murata; Manufacturer_Part_Number: GRM21BR61C106KE15L; Digi_PN: 14050701; Component_Life_Cycle_State: Proven; Area: 3.99; Project: Adjustable Foundation; Tolerance: 10
J7 = 1001118: CONN TRANSFLSH R/A PUSH-PUSH SMD; Part_Type: Connector; Manufacturer: Molex; Digi_PN: MB03015; Component_Life_Cycle_State: Reviewed; Area: 213; Project: CCWMX6_SBC board
J12 = 1001130: SMCONN,MINI PCI EXP, 6.8MM HT; Part_Type: Connector; Manufacturer: Foxconn; Digi_PN: 18000349; Component_Life_Cycle_State: Reviewed; Area: 150; Project: CCWMX6_SBC board
J14 = 1001120: MEMORY CARD 6POS PUSH/PULL SMD; Part_Type: Connector; Manufacturer: Molex; Digi_PN: 18000638; Component_Life_Cycle_State: Reviewed; Area: 217; Project: CCWMX6_SBC board
L1 = 1001912: FIXED IND 1.5UH 4.5A 42 MOHM SMD; Manufacturer: Bourns; Manufacturer_Part_Number: SRP4020TA-1R5M; Digi_PN: 21000530; Component_Life_Cycle_State: Reviewed; Area: 24.75; Project: CCWMX6_SBC board; Tolerance: ±20%
Q6 = 1000715: MOSFET N-CH 60V 115MA SOT-523F; Part_Type: Transistor; Manufacturer: Fairchild Semiconductor; Digi_PN: 17050797; Component_Life_Cycle_State: CAD Reviewed; Area: 3.06; Project: SmartMeter2; Note: 17050841 = Digi No. for GE WDNU
R30 = 1001149: RES 22.1K OHM 1/16W 1% 0402 SMD; Part_Type: Resistor; Manufacturer: Vishay Dale; Manufacturer_Part_Number: CRCW040222K1FKED; Digi_PN: 13050450; Component_Life_Cycle_State: Reviewed; Area: 0.95; Project: CCWMX6_SBC board; Power_WV_SRF: 0.063; Tolerance: ±100ppm/°C
R31-R34 R185 R241 = 1000537: as R38 on sheet 02 - CCIMX6UL Module
R35 = 1000467: as R8 on sheet 03 - Power, boot strap, reset
R137 R138 = 1000701: RES 470K OHM 1/10W 1% 0402 SMD; Part_Type: Resistor; Manufacturer: Panasonic - ECG; Manufacturer_Part_Number: ERJ-2RKF4703X; Digi_PN: 13051092; Component_Life_Cycle_State: CAD Reviewed; Area: 0.95; Project: KITT; Power_WV_SRF: 100
R139 R140 R186 = 1000480: as R22 on sheet 03 - Power, boot strap, reset
R141 R243-R246 = 1000076: as R42 on sheet 02 - CCIMX6UL Module
R142 = 1001916: RES SMD 2 OHM 5% 1/10W 0603; Part_Type: Resistor; Manufacturer: Panasonic - ECG; Manufacturer_Part_Number: ERJ-3GEYJ2R0V; Digi_PN: 13050488; Component_Life_Cycle_State: Reviewed; Area: 4.5; Project: CCWMX6_SBC board; Power_WV_SRF: 100; Tolerance: 1
R143 = 1001518: RES 53.6K OHM 1/10W 1% 0603 SMD; Part_Type: Resistor; Manufacturer: Panasonic - ECG; Manufacturer_Part_Number: ERJ-3EKF5362V; Digi_PN: 13051064; Component_Life_Cycle_State: Reviewed; Area: 2.5; Project: WDNU-II
R144 = 1001200: RES 12.0K OHM 1/10W 1% 0603 SMD; Part_Type: Resistor; Manufacturer: Yageo; Manufacturer_Part_Number: RC0603FR-0712KL; Digi_PN: 13050531; Component_Life_Cycle_State: Reviewed; Area: 2.5; Project: LuCoV2; Power_WV_SRF: 100; Tolerance: 1
R223 = 1000208: as R1 on sheet 02 - CCIMX6UL Module
U2 = 1000965: eMMC 4GB, -25/85°C, 153FBGA; MPN: SANDISK SDIN7DP2-4G; Part_Type: IC; Manufacturer: Sandisk; Manufacturer_Part_Number: SDIN7DP2-4G; DIGI Item Number: NA; Digi_PN: 16051816; Component_Life_Cycle_State: Reviewed; Area: 149,5; Project: ConnectCore i.MX6 module
U4 = 1001163: MOSFET P-CH 20V 3.7A SOT23-3; Part_Type: IC; Manufacturer: Vishay Siliconix; Digi_PN: 17050358; Component_Life_Cycle_State: Reviewed; Area: 10.92; Project: CCWMX6_SBC board
U23 = 1001907: IC REG BUCK ADJ 3A SYNC; Manufacturer: Linear Technology; Manufacturer_Part_Number: MP2316GD; Digi_PN: 17050862; Component_Life_Cycle_State: Reviewed; Area: 9.375; Project: CCWMX6_SBC board
U33 U34 = 1001179: IC SWITCH SPDT SC88; Manufacturer: On Semiconductor; Digi_PN: 16051954; Component_Life_Cycle_State: Reviewed; Project: CCWMX6_SBC board; Area: 4.8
